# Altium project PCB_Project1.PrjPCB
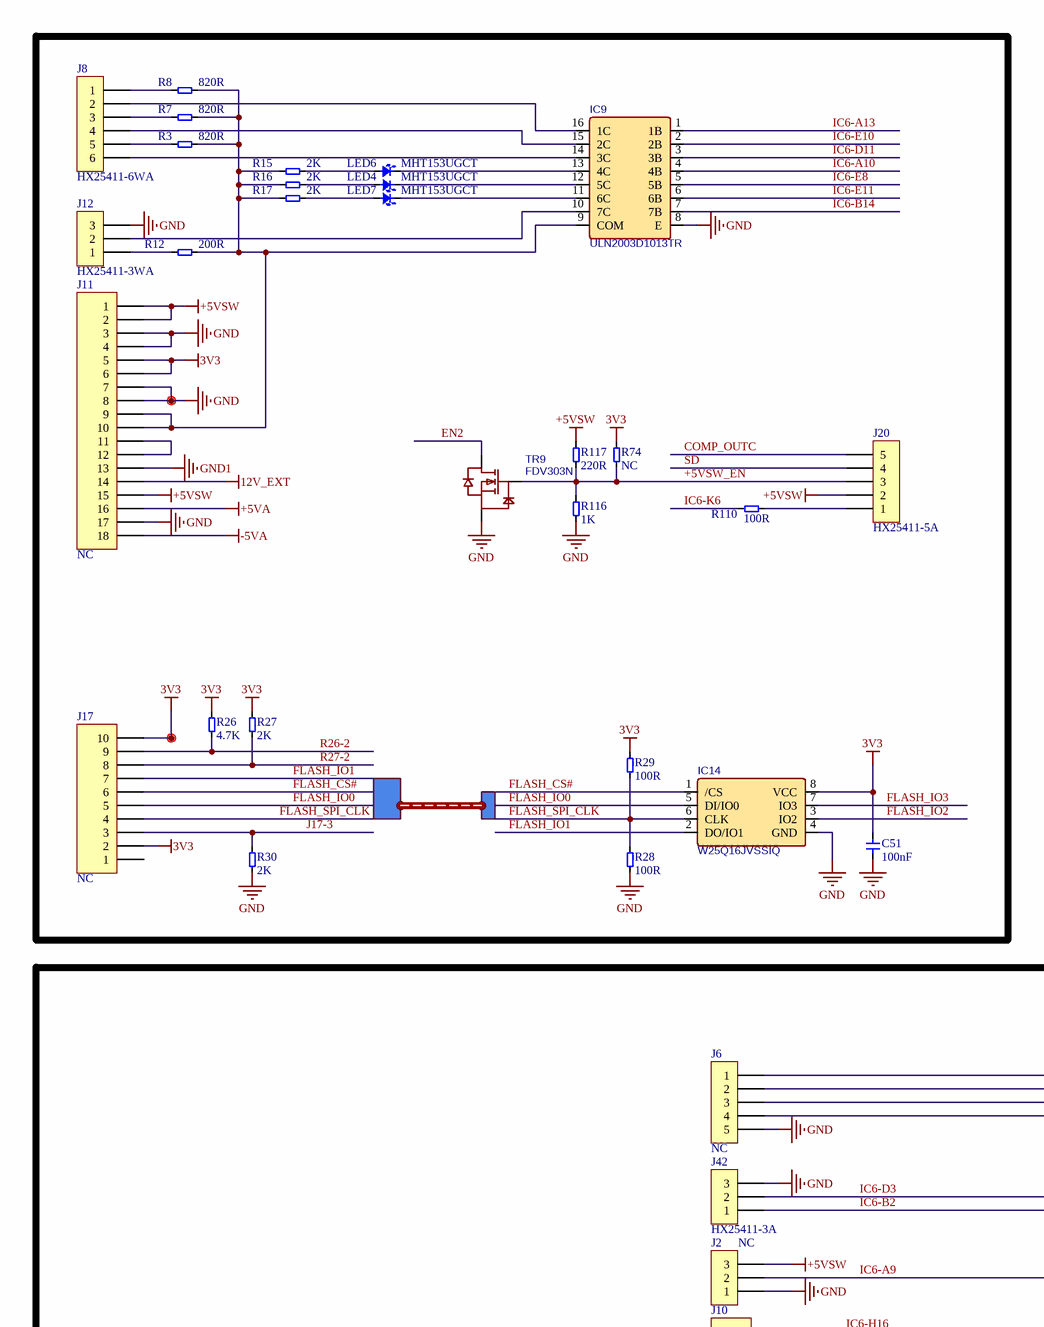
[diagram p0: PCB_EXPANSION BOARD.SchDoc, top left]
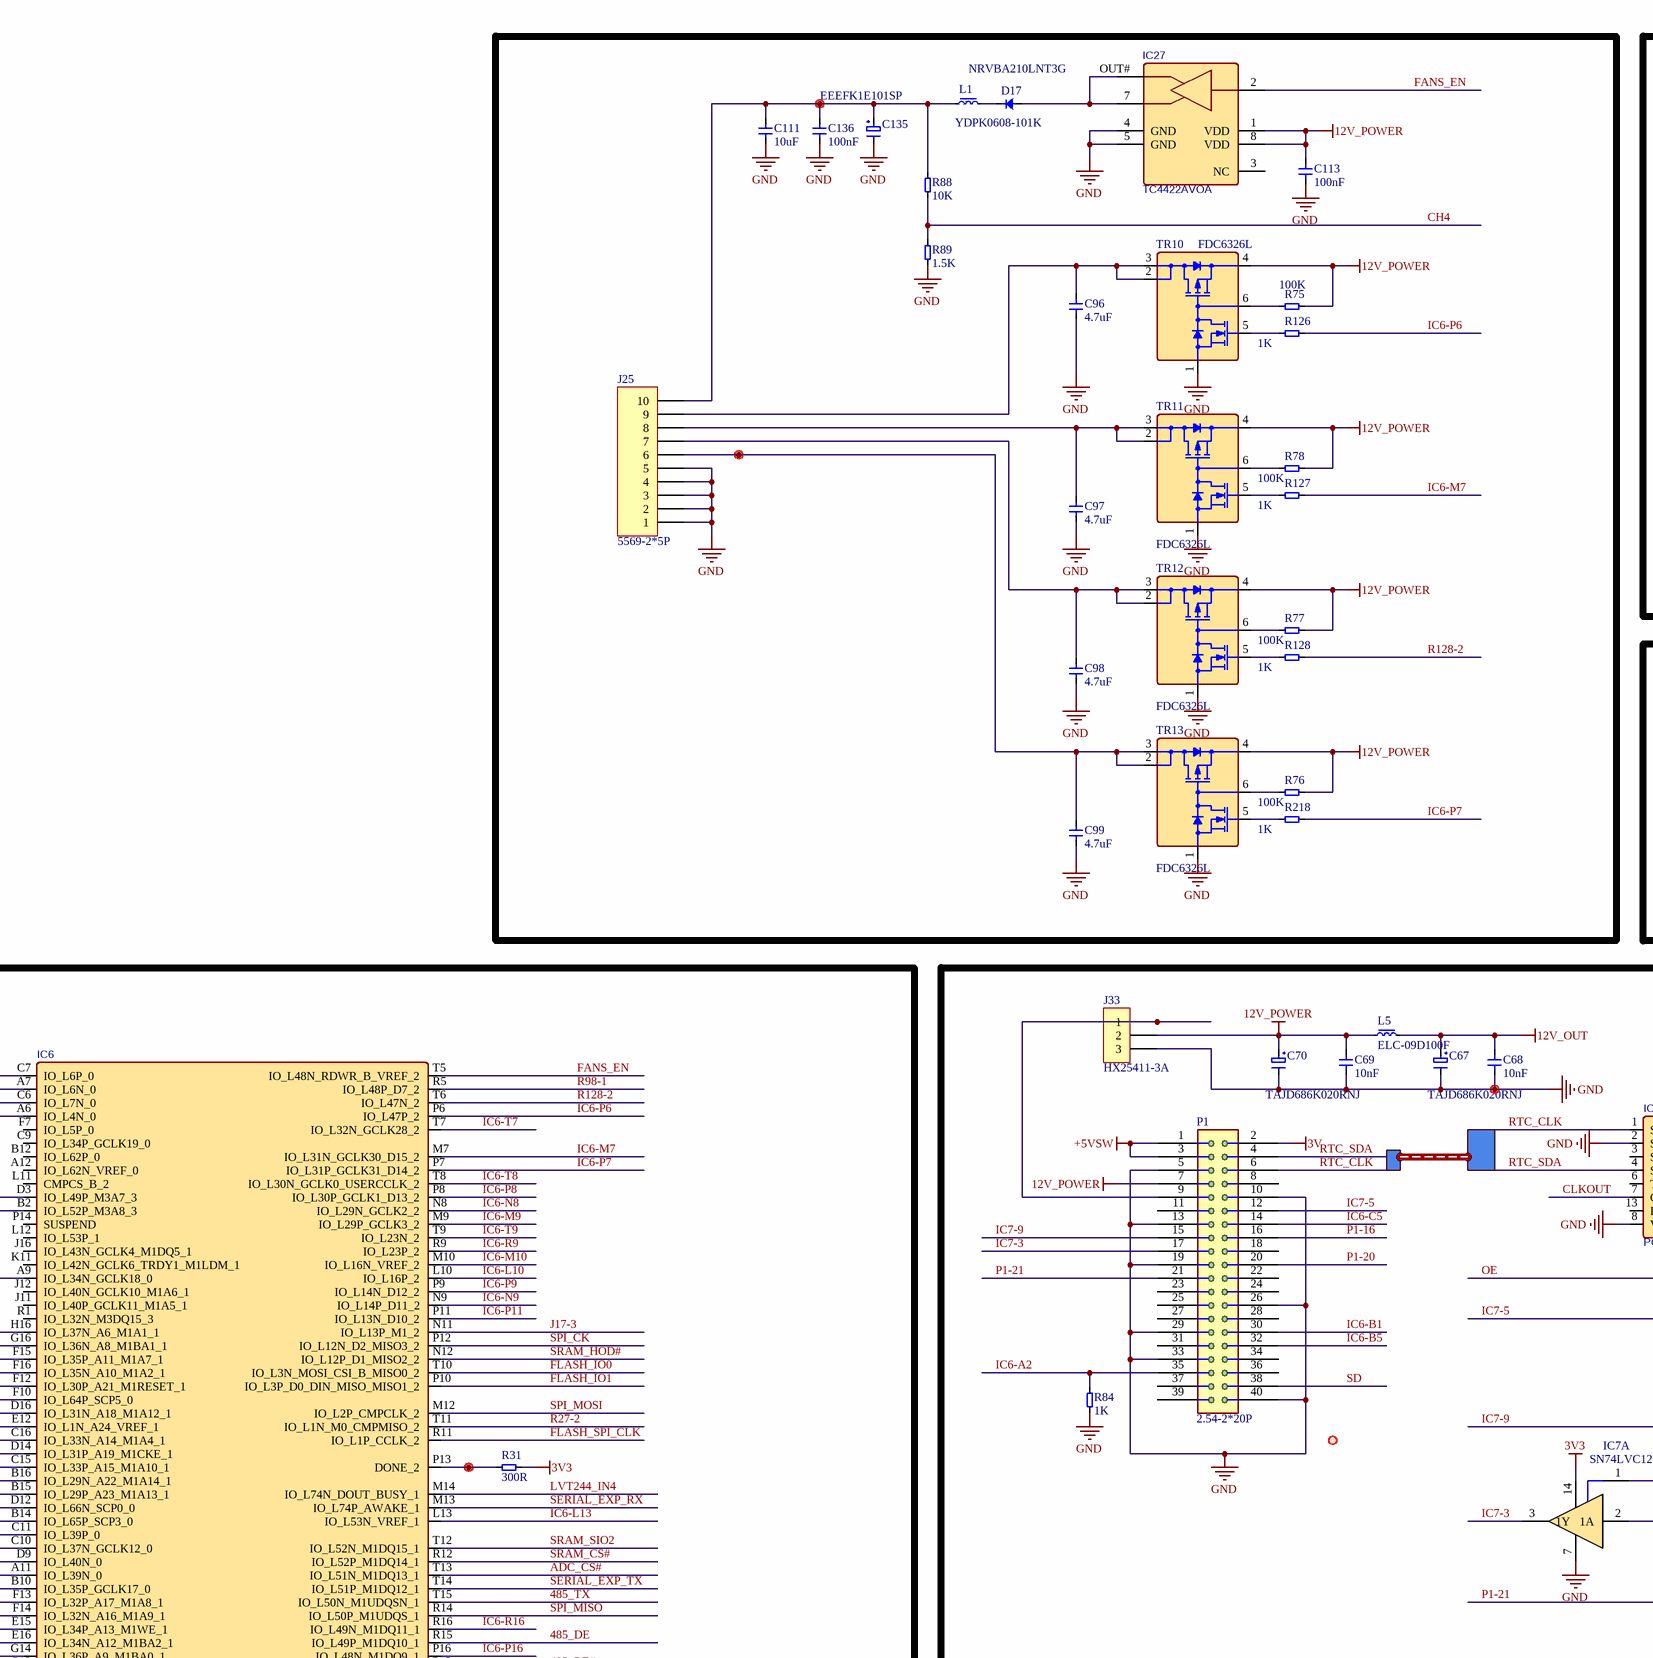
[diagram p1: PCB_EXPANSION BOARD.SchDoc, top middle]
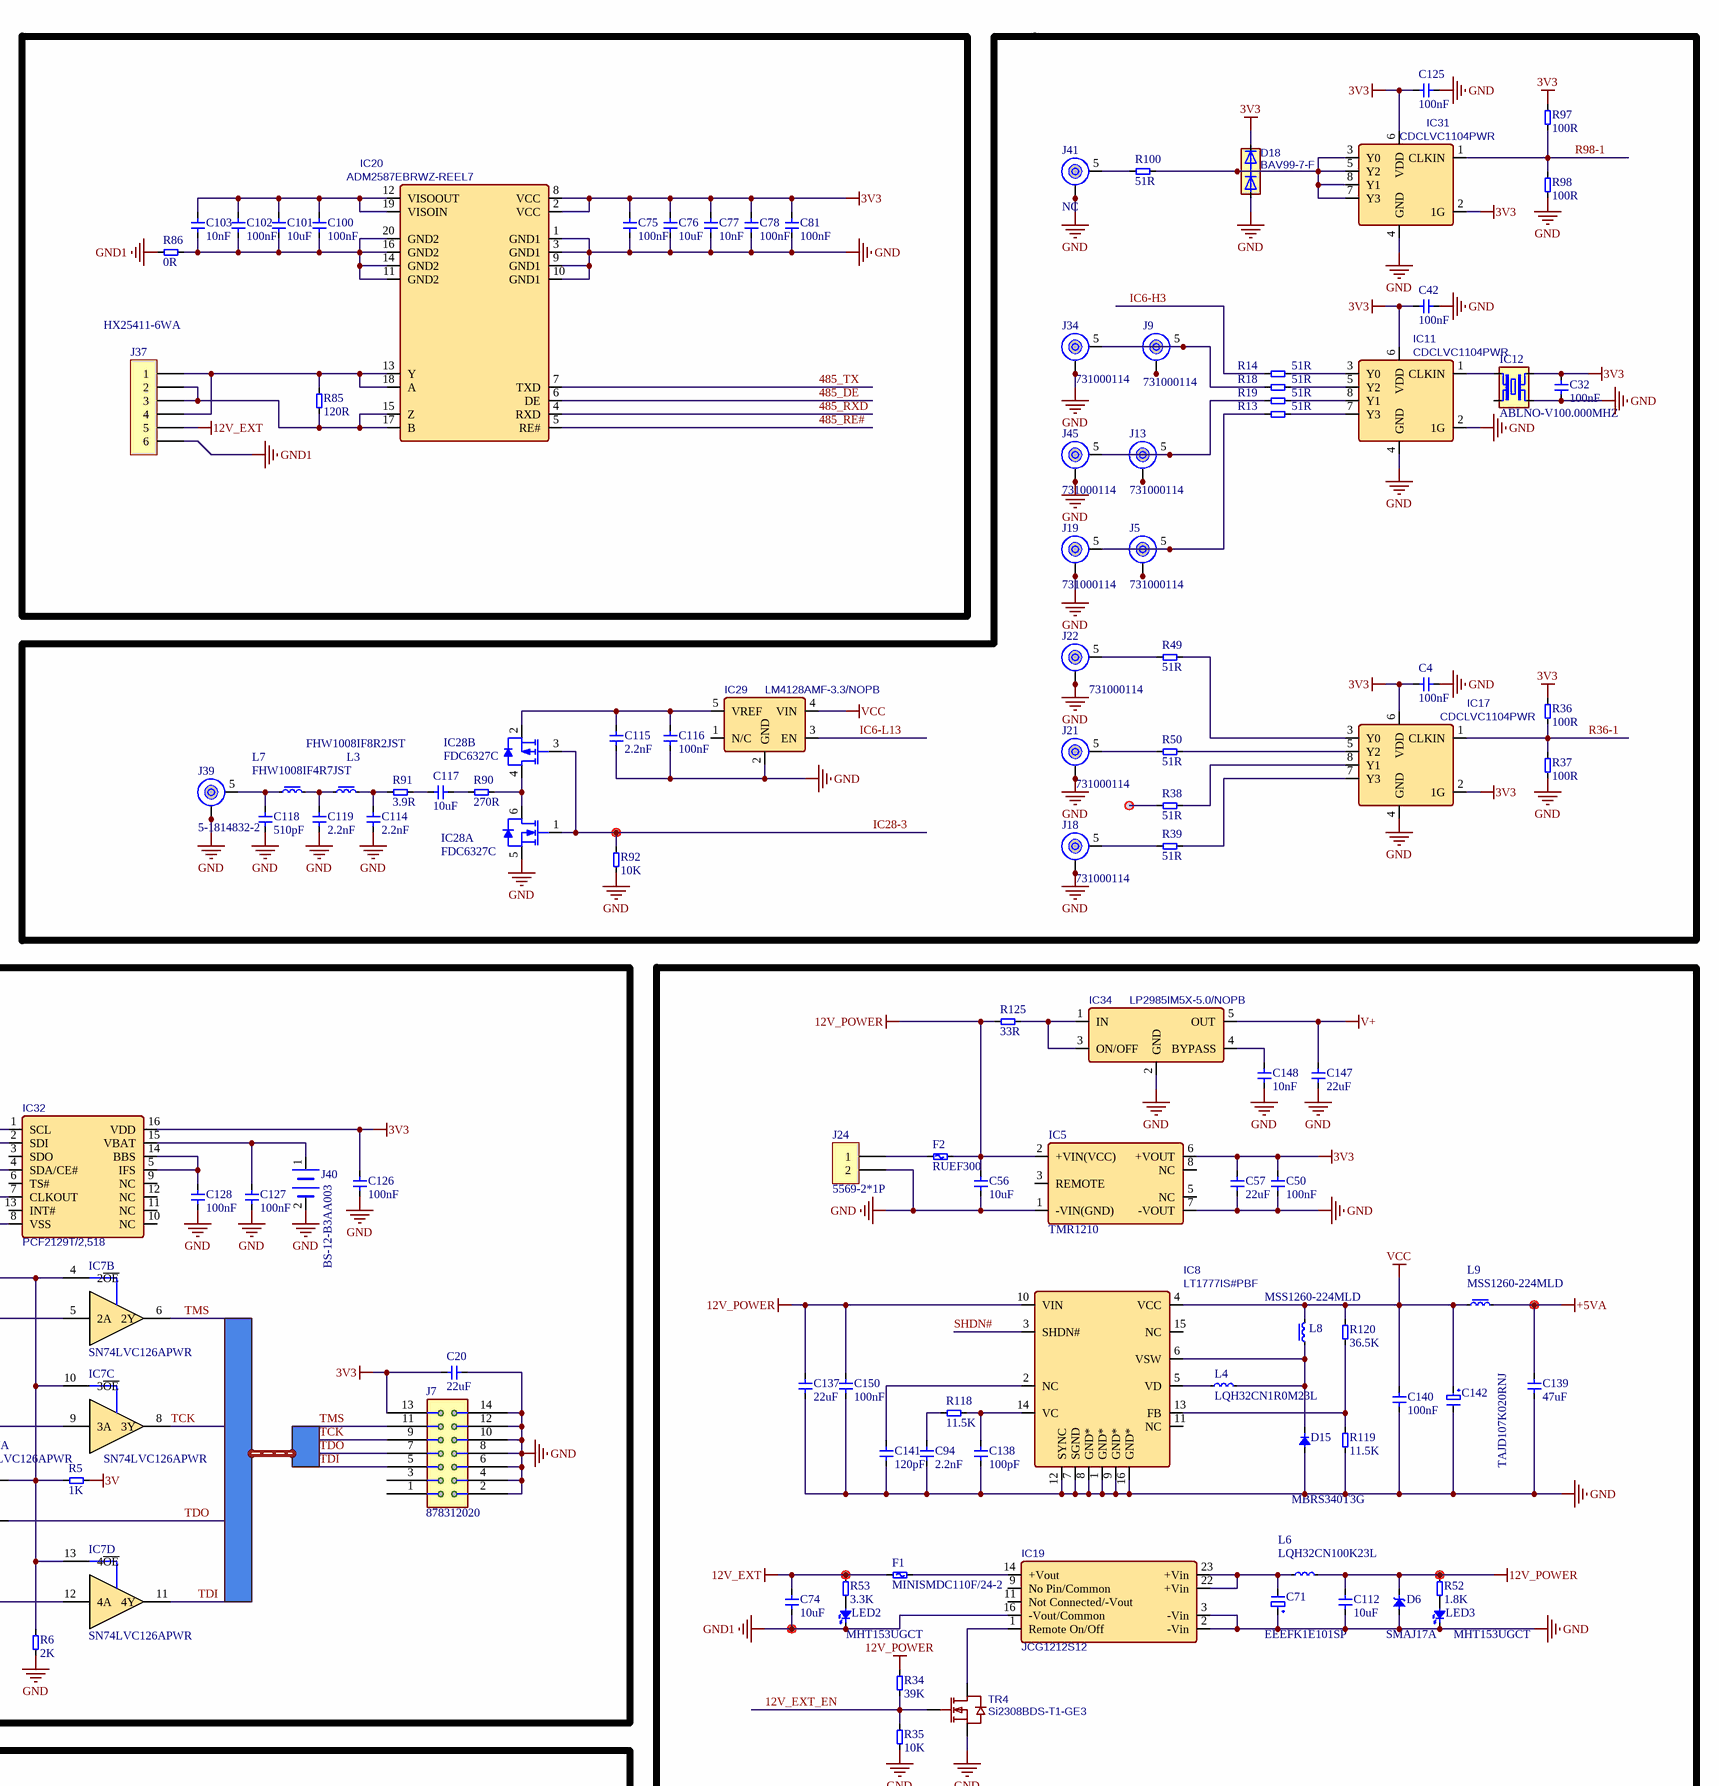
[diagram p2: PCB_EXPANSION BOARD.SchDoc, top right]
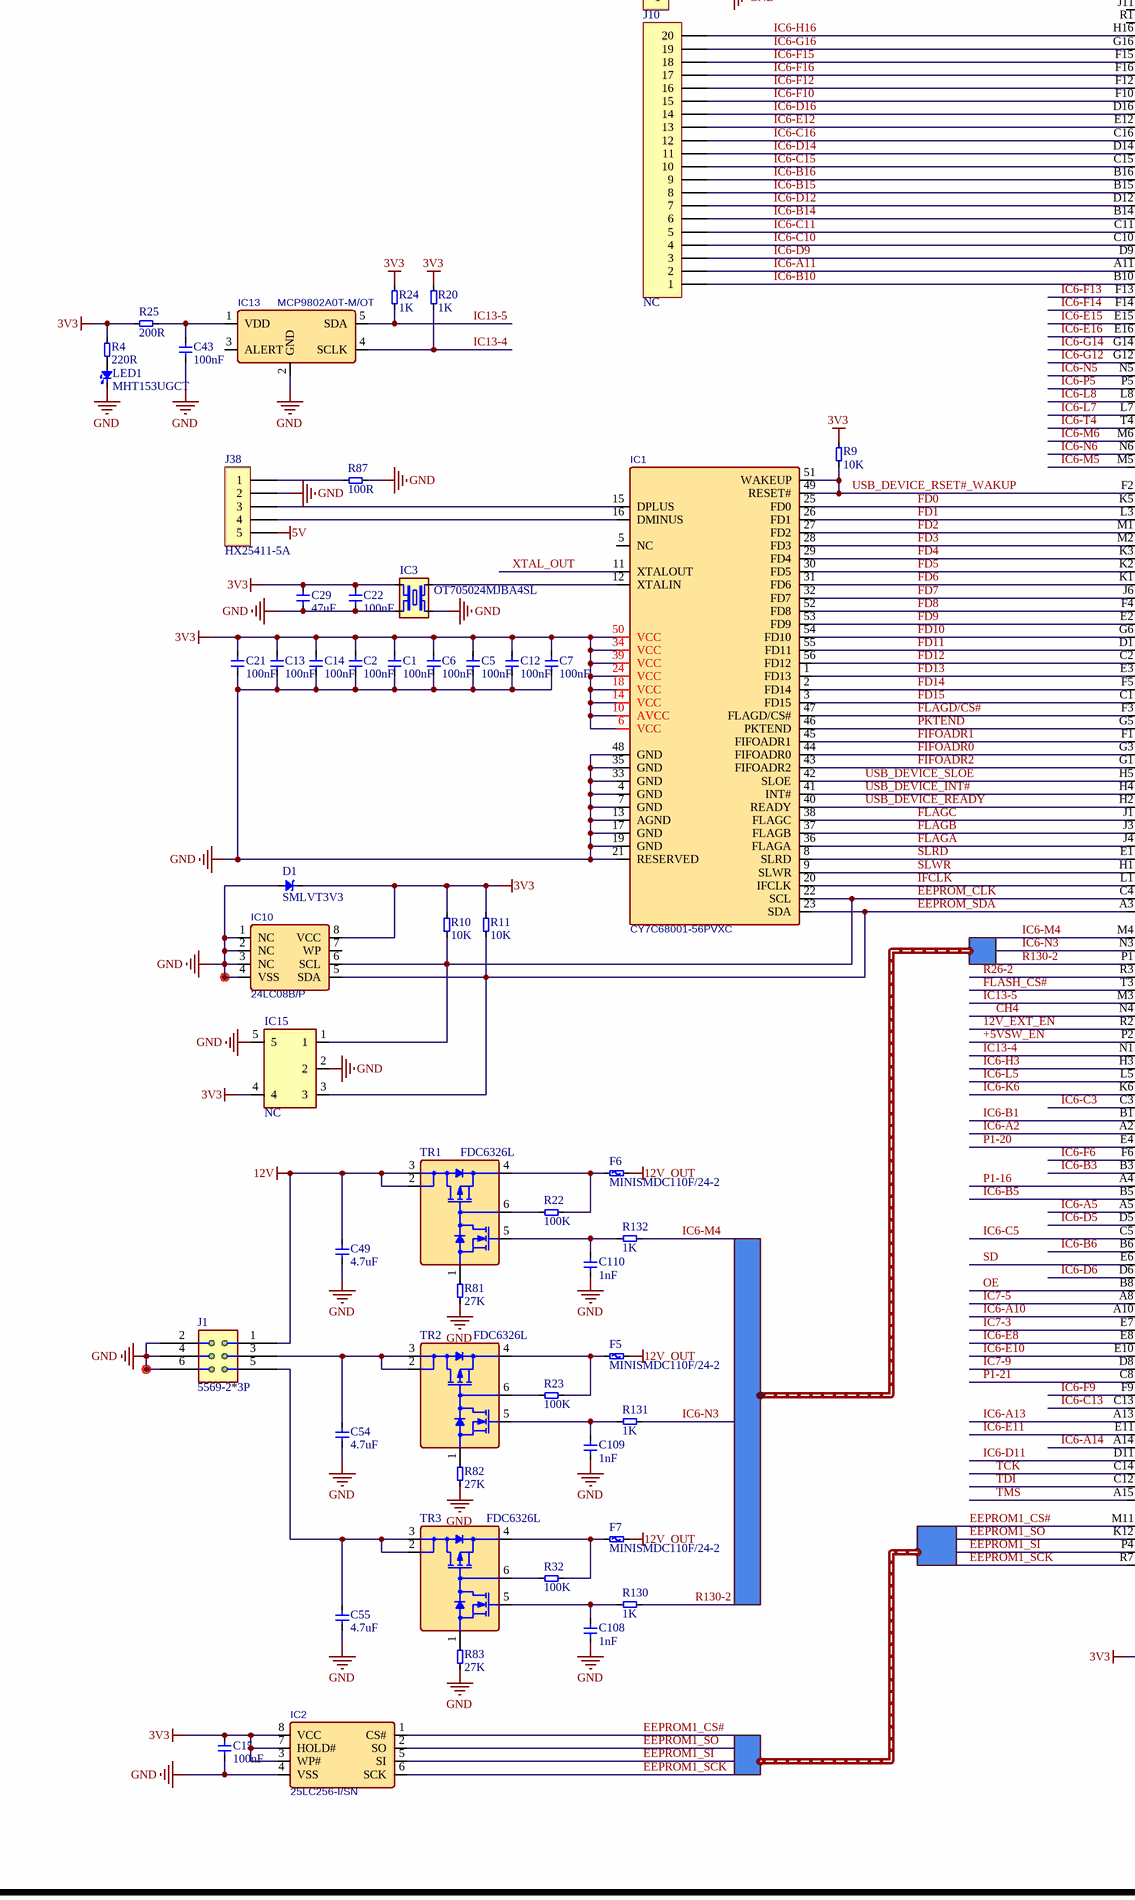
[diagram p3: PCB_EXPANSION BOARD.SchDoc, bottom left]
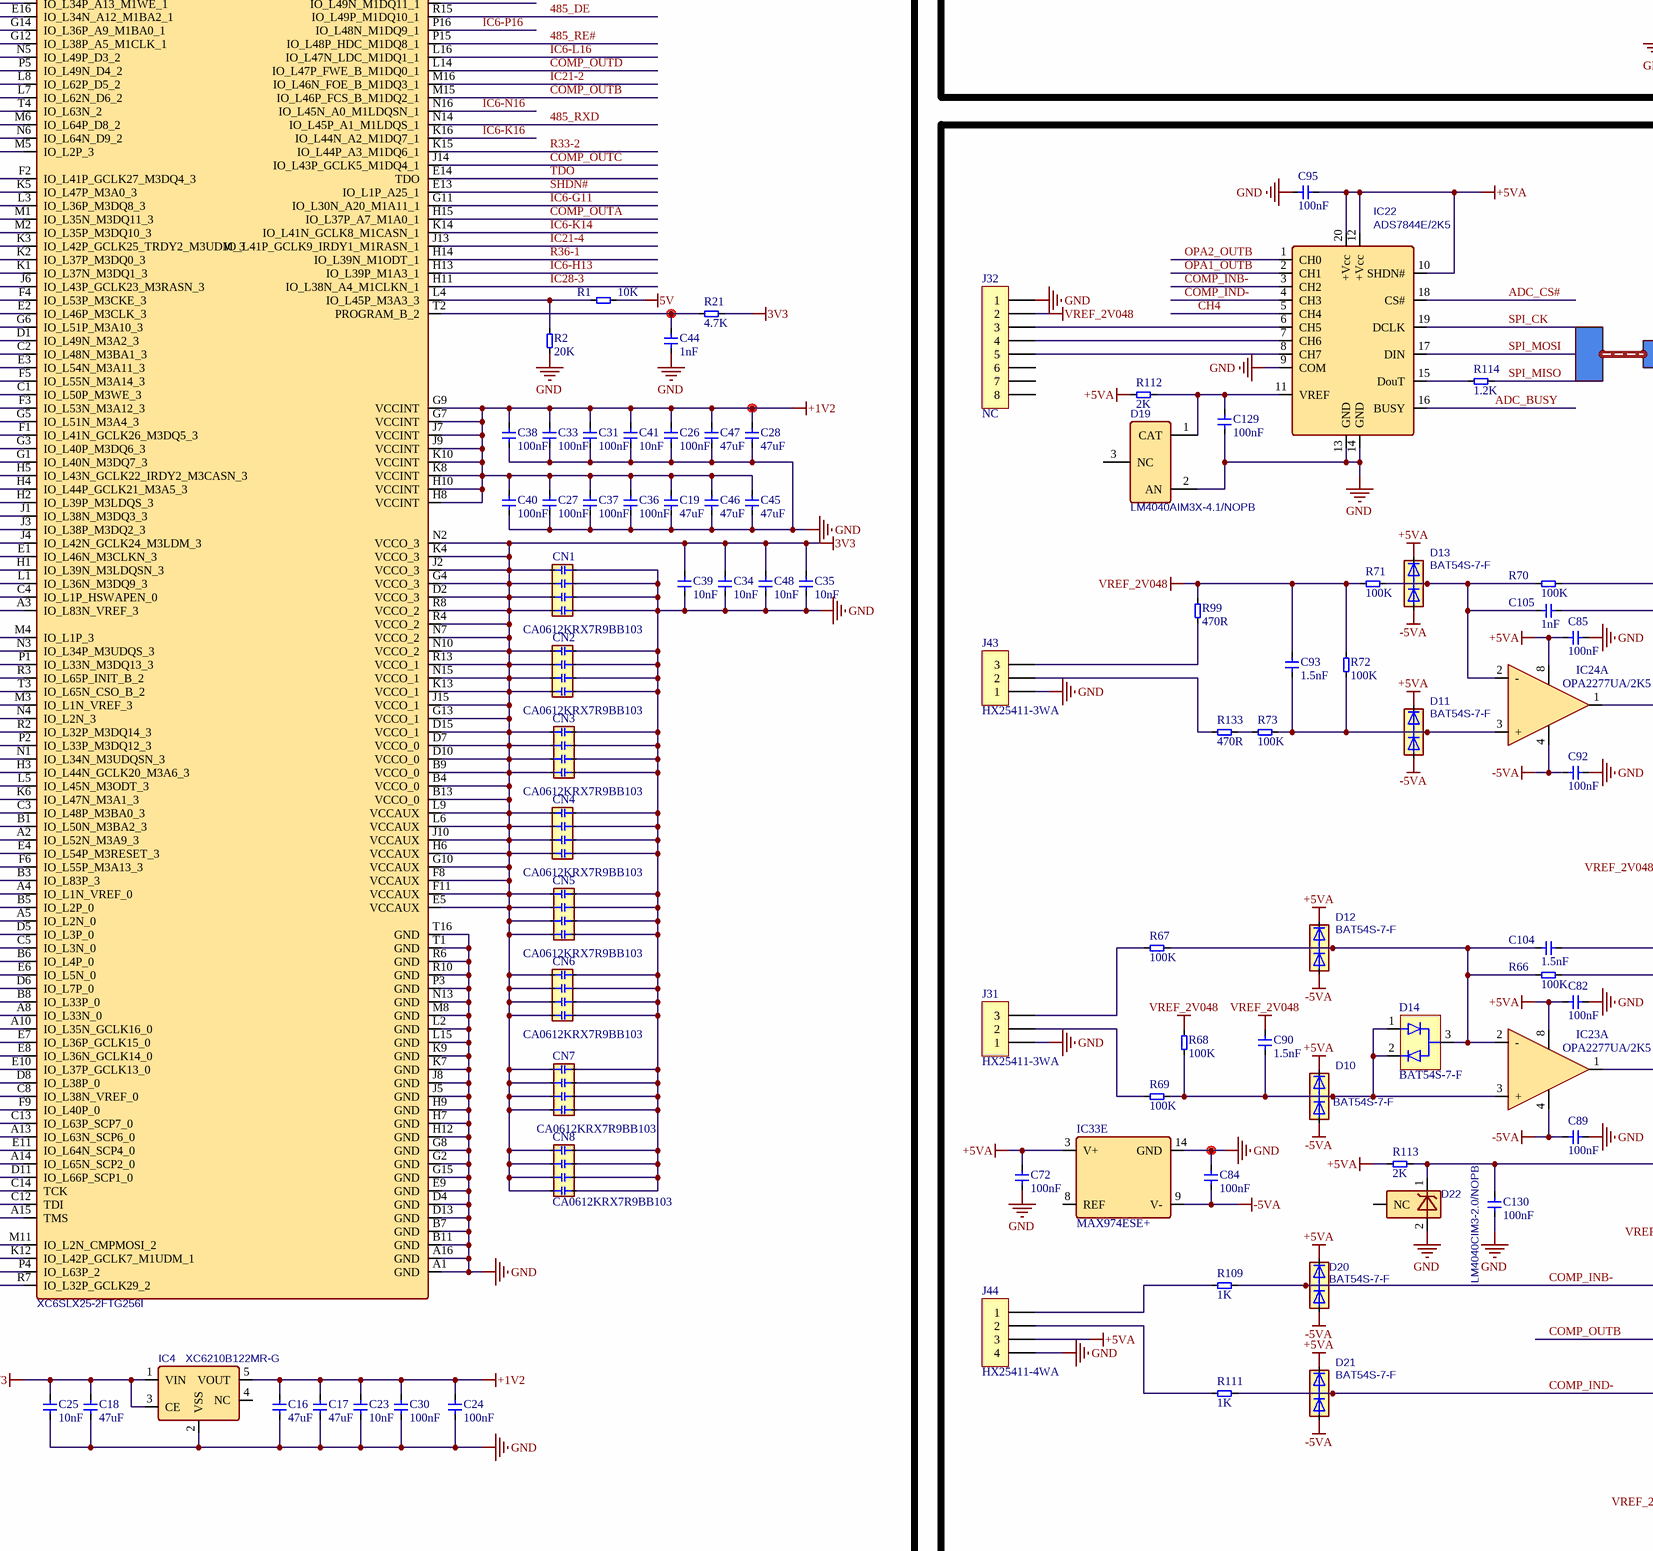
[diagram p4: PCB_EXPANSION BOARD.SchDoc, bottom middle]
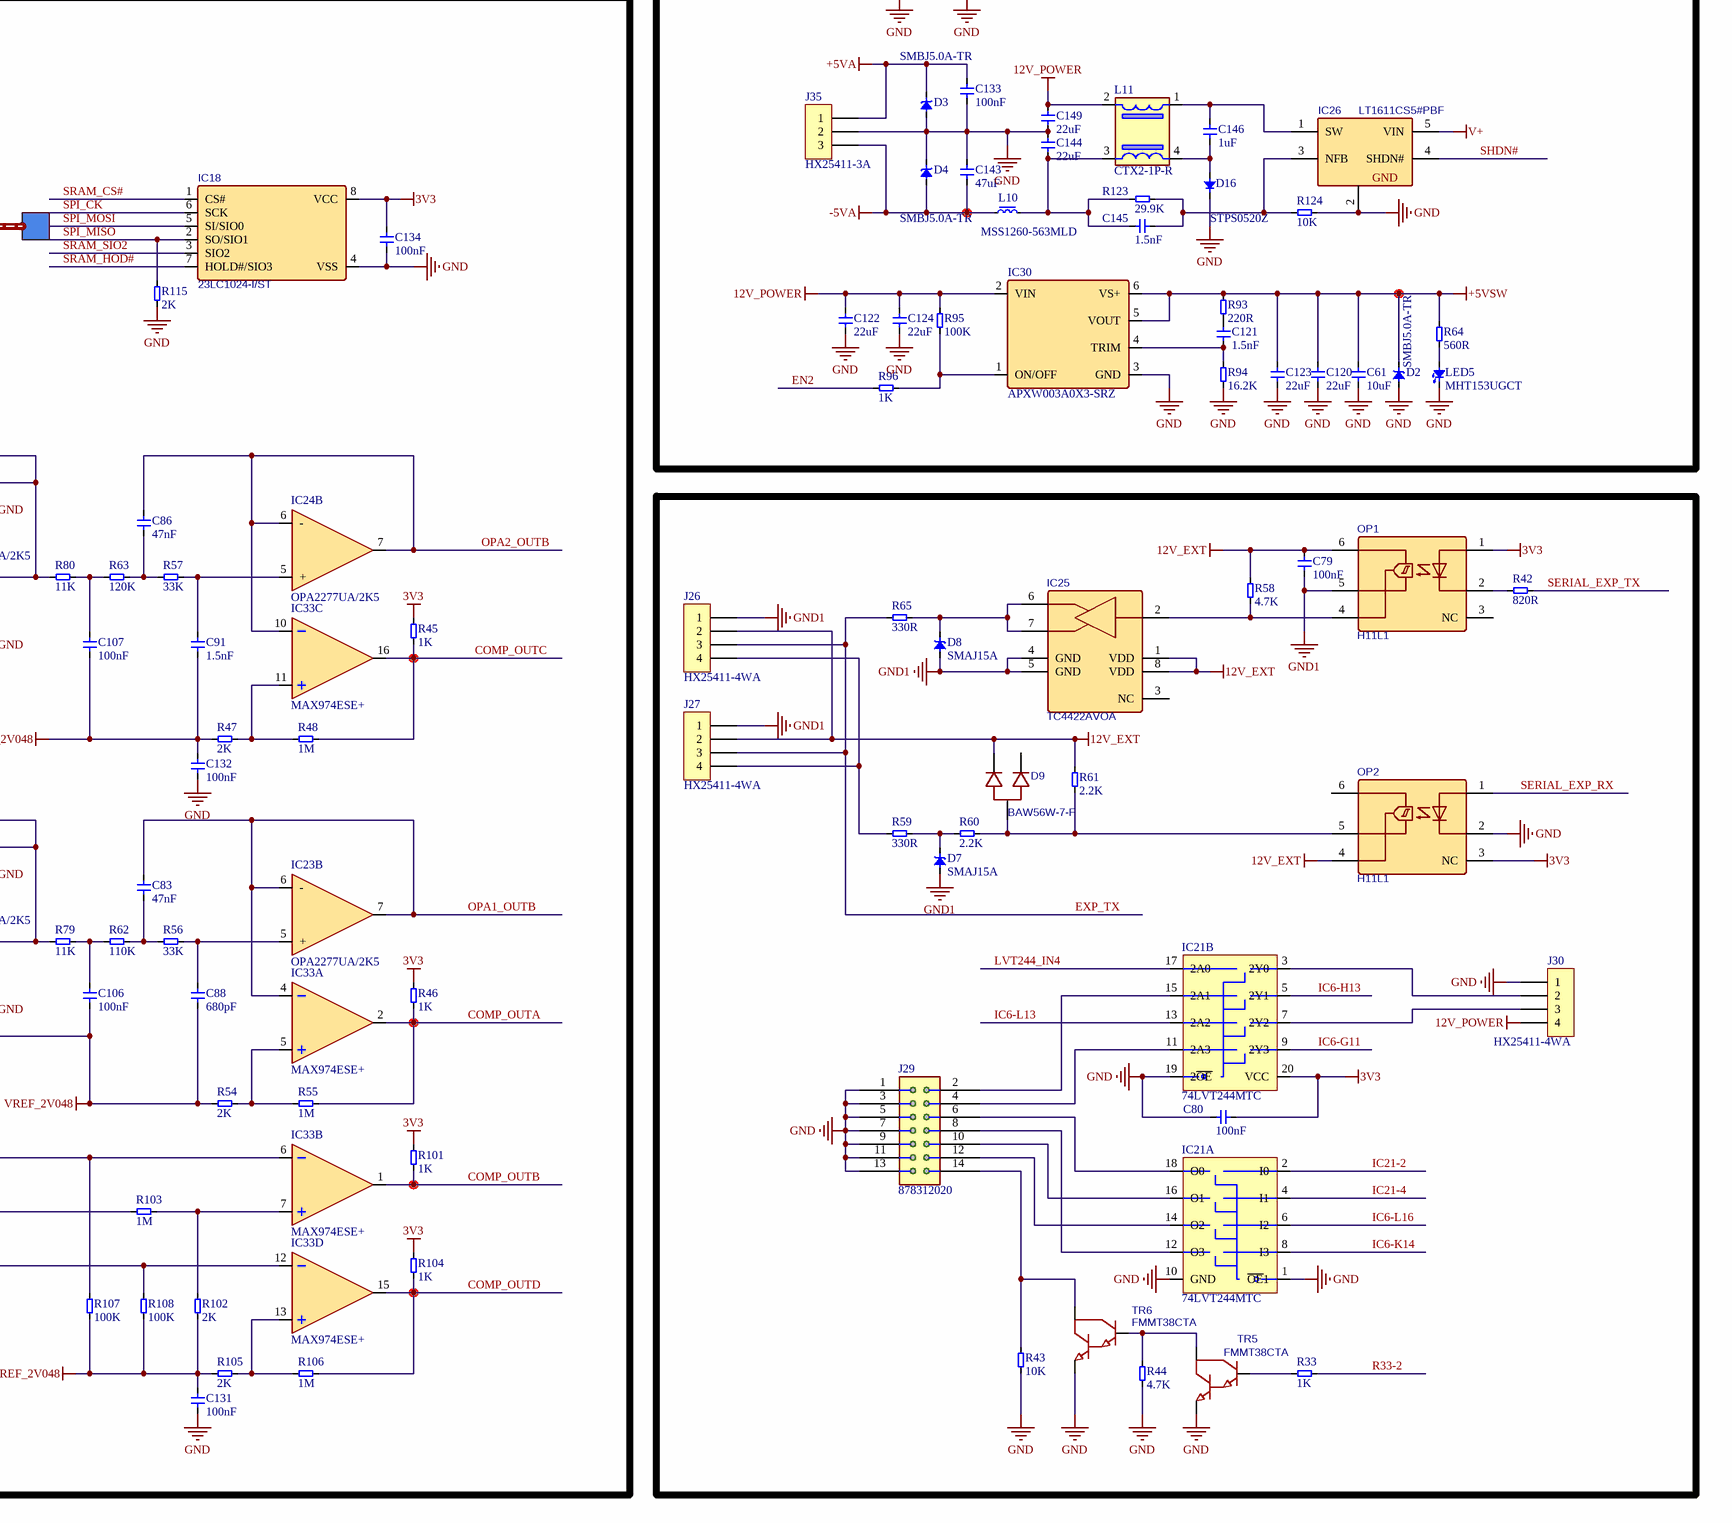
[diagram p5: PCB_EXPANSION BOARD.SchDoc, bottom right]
1 sheet, 420 parts. Net scope: global (net labels, ports and power ports of the same name join across sheets).
Board file: PCB_EXPANSION BOARD.PcbDoc

## Sheet PCB_EXPANSION BOARD.SchDoc
size 861 x 624 mm

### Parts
C1  100nF  [C0603]
C2  100nF  [C0603]
C4  100nF  [C 1206_L]
C5  100nF  [C0603]
C6  100nF  [C0603]
C7  100nF  [C0603]
C12  100nF  [C0603]
C13  100nF  [C0603]
C14  100nF  [C0603]
C15  100nF  [C0603]
C16  47uF  [C 1206_L]
C17  47uF  [C 1206_L]
C18  47uF  [C 1206_L]
C19  47uF  [C 1206_L]
C20  22uF  [C 1206_L]
C21  100nF  [C0603]
C22  100nF  [C0603]
C23  10nF  [C0603]
C24  100nF  [C0603]
C25  10nF  [C0603]
C26  100nF  [C0603]
C27  100nF  [C0603]
C28  47uF  [C 1206_L]
C29  47uF  [C 1206_L]
C30  100nF  [C0603]
C31  100nF  [C0603]
C32  100nF  [C0805]
C33  100nF  [C0603]
C34  10nF  [C0603]
C35  10nF  [C0603]
C36  100nF  [C0603]
C37  100nF  [C0603]
C38  100nF  [C0603]
C39  10nF  [C0603]
C40  100nF  [C0603]
C41  10nF  [C0603]
C42  100nF  [C0805]
C43  100nF  [C0805]
C44  1nF  [C 1206_L]
C45  47uF  [C 1206_L]
C46  47uF  [C 1206_L]
C47  47uF  [C 1206_L]
C48  10nF  [C0603]
C49  4.7uF  [C0805]
C50  100nF  [C0805]
C51  100nF  [C0603]
C54  4.7uF  [C0805]
C55  4.7uF  [C0805]
C56  10uF  [C 1206_L]
C57  22uF  [C 1206_L]
C61  10uF  [C 1206_L]
C67  TAJD686K020RNJ  [C_7343H]
C68  10nF  [C 1206_L]
C69  10nF  [C 1206_L]
C70  TAJD686K020RNJ  [C_7343H]
C71  EEEFK1E101SP  [CAP-SMD_BD6.3]
C72  100nF  [C0603]
C74  10uF  [C 1206_L]
C75  100nF  [C0805]
C76  10uF  [C 1206_L]
C77  10nF  [C0805]
C78  100nF  [C0805]
C79  100nF  [C0805]
C80  100nF  [C0805]
C81  100nF  [C0805]
C82  100nF  [C0603]
C83  47nF  [C0603]
C84  100nF  [C0603]
C85  100nF  [C0603]
C86  47nF  [C0603]
C88  680pF  [C0603]
C89  100nF  [C0603]
C90  1.5nF  [C0603]
C91  1.5nF  [C0603]
C92  100nF  [C0603]
C93  1.5nF  [C0603]
C94  2.2nF  [C0603]
C95  100nF  [C0603]
C96  4.7uF  [C0805]
C97  4.7uF  [C0805]
C98  4.7uF  [C0805]
C99  4.7uF  [C0805]
C100  100nF  [C0805]
C101  10uF  [C 1206_L]
C102  100nF  [C0805]
C103  10nF  [C0805]
C104  1.5nF  [C0603]
C105  1nF  [C0603]
C106  100nF  [C0603]
C107  100nF  [C0603]
C108  1nF  [C0603]
C109  1nF  [C0603]
C110  1nF  [C0603]
C111  10uF  [C1206]
C112  10uF  [C 1206_L]
C113  100nF  [C0603]
C114  2.2nF  [C0603]
C115  2.2nF  [C 1206_L]
C116  100nF  [C0603]
C117  10uF  [C 1206_L]
C118  510pF  [C0805]
C119  2.2nF  [C0603]
C120  22uF  [C 1206_L]
C121  1.5nF  [C0603]
C122  22uF  [C 1206_L]
C123  22uF  [C 1206_L]
C124  22uF  [C 1206_L]
C125  100nF  [C0805]
C126  100nF  [C0805]
C127  100nF  [C0805]
C128  100nF  [C0805]
C129  100nF  [C0603]
C130  100nF  [C0603]
C131  100nF  [C0603]
C132  100nF  [C0603]
C133  100nF  [C0603]
C134  100nF  [C0805]
C135  EEEFK1E101SP  [CAP-SMD_BD6.3]
C136  100nF  [C0603]
C137  22uF  [C 1206_L]
C138  100pF  [C0603]
C139  47uF  [C 1210_L]
C140  100nF  [C0603]
C141  120pF  [C0603]
C142  TAJD107K020RNJ  [C_7343H]
C143  47uF  [C 1210_L]
C144  22uF  [C 1206_L]
C145  1.5nF  [C0603]
C146  1uF  [C0603]
C147  22uF  [C 1206_L]
C148  10nF  [C0603]
C149  22uF  [C 1206_L]
C150  100nF  [C0603]
CN1  CA0612KRX7R9BB103  [CAP-ARRAY-0612-8P]
CN2  CA0612KRX7R9BB103  [CAP-ARRAY-0612-8P]
CN3  CA0612KRX7R9BB103  [CAP-ARRAY-0612-8P]
CN4  CA0612KRX7R9BB103  [CAP-ARRAY-0612-8P]
CN5  CA0612KRX7R9BB103  [CAP-ARRAY-0612-8P]
CN6  CA0612KRX7R9BB103  [CAP-ARRAY-0612-8P]
CN7  CA0612KRX7R9BB103  [CAP-ARRAY-0612-8P]
CN8  CA0612KRX7R9BB103  [CAP-ARRAY-0612-8P]
D1  SMLVT3V3  [SMB]
D2  SMBJ5.0A-TR  [SMB]
D3  SMBJ5.0A-TR  [SMB]
D4  SMBJ5.0A-TR  [SMB]
D6  SMAJ17A  [SMA]
D7  SMAJ15A  [SMA]
D8  SMAJ15A  [SMA]
D9  BAW56W-7-F  [SOT323]
D10  BAT54S-7-F  [SOT-23-3]
D11  BAT54S-7-F  [SOT-23-3]
D12  BAT54S-7-F  [SOT-23-3]
D13  BAT54S-7-F  [SOT-23-3]
D14  BAT54S-7-F  [SOT-23-3]
D15  MBRS340T3G  [SMC]
D16  STPS0520Z  [SOD-123]
D17  NRVBA210LNT3G  [SMA]
D18  BAV99-7-F  [SOT-23-3]
D19  LM4040AIM3X-4.1/NOPB  [SOT-23-3]
D20  BAT54S-7-F  [SOT-23-3]
D21  BAT54S-7-F  [SOT-23-3]
D22  LM4040CIM3-2.0/NOPB  [SOT-23-3]
F1  MINISMDC110F/24-2  [F1812]
F2  RUEF300  [FUSE-TH_L11.2-W3.1]
F5  MINISMDC110F/24-2  [F1812]
F6  MINISMDC110F/24-2  [F1812]
F7  MINISMDC110F/24-2  [F1812]
IC1  CY7C68001-56PVXC  [SSOP-56]
IC2  25LC256-I/SN  [SOIC-8]
IC3  OT705024MJBA4SL  [OSC-SMD_4P-L7.0-W5.0-BL]
IC4  XC6210B122MR-G  [SOT-23-5]
IC5  TMR1210  [PWRM-TH_TRACOPOWER_TMR]
IC6  XC6SLX25-2FTG256I  [FBGA-256_L17.0-W17.0]
IC7  SN74LVC126APWR  [TSSOP14]  (parts A,B,C,D of 4)
IC8  LT1777IS#PBF  [SOP16]
IC9  ULN2003D1013TR  [SOP16]
IC10  24LC08B/P  [DIP-8]
IC11  CDCLVC1104PWR  [TSSOP8]
IC12  ABLNO-V100.000MHZ  [OSC-SMD_4P-L14.3-W8.7-BL]
IC13  MCP9802A0T-M/OT  [SOT-23-5]
IC14  W25Q16JVSSIQ  [SOIC-8W]
IC15  NC  [SOT-23-5]
IC17  CDCLVC1104PWR  [TSSOP8]
IC18  23LC1024-I/ST  [TSSOP8]
IC19  JCG1212S12  [PM_JCG1212S12]
IC20  ADM2587EBRWZ-REEL7  [SOIC-20_L13.0-W7.6]
IC21  74LVT244MTC  [TSSOP20]  (parts A,B of 2)
IC22  ADS7844E/2K5  [SSOP-20]
IC23  OPA2277UA/2K5  [SOIC-8]  (parts A,B of 2)
IC24  OPA2277UA/2K5  [SOIC-8]  (parts A,B of 2)
IC25  TC4422AVOA  [SOIC-8]
IC26  LT1611CS5#PBF  [SOT-23-5]
IC27  TC4422AVOA  [SOIC-8]
IC28  FDC6327C  [SOT-23-6]  (parts A,B of 2)
IC29  LM4128AMF-3.3/NOPB  [SOT-23-5]
IC30  APXW003A0X3-SRZ  [PM_APXW003]
IC31  CDCLVC1104PWR  [TSSOP8]
IC32  PCF2129T/2,518  [SO-16]
IC33  MAX974ESE+  [SOP16]  (parts A,B,C,D,E of 5)
IC34  LP2985IM5X-5.0/NOPB  [SOT-23-5]
J1  5569-2*3P  [CONN-TH_HAA420A-6AW]
J2  NC  [XH2.54-LI-3P]
J5  731000114  [ANT-TH_KH-SMA-K513-G]
J6  NC  [HDR2.54-LI-5P]
J7  878312020  [PHD2.0-LI-2x7P]
J8  HX25411-6WA  [CONN-TH_KF2510-6AGW]
J9  731000114  [ANT-TH_KH-SMA-K513-G]
J10  NC  [HDR2.54-LI-20P]
J11  NC  [HDR2.54-LI-18P]
J12  HX25411-3WA  [CONN-TH_KF2510-3AGW]
J13  731000114  [ANT-TH_KH-SMA-K513-G]
J17  NC  [HDR2.54-LI-10P]
J18  731000114  [ANT-TH_KH-SMA-K513-G]
J19  731000114  [ANT-TH_KH-SMA-K513-G]
J20  HX25411-5A  [KF2510-LI-5P]
J21  731000114  [ANT-TH_KH-SMA-K513-G]
J22  731000114  [ANT-TH_KH-SMA-K513-G]
J24  5569-2*1P  [CONN-TH_2P-P4.20_5557-2X1AW]
J25  5569-2*5P  [CONN-TH_DLL-5569-10AWS]
J26  HX25411-4WA  [CONN-TH_KF2510-4AGW]
J27  HX25411-4WA  [CONN-TH_KF2510-4AGW]
J29  878312020  [PHD2.0-LI-2x7P]
J30  HX25411-4WA  [CONN-TH_KF2510-4AGW]
J31  HX25411-3WA  [CONN-TH_KF2510-3AGW]
J32  NC  [HDR2.54-LI-8P]
J33  HX25411-3A  [KF2510-LI-3P]
J34  731000114  [ANT-TH_KH-SMA-K513-G]
J35  HX25411-3A  [KF2510-LI-3P]
J37  HX25411-6WA  [CONN-TH_KF2510-6AGW]
J38  HX25411-5A  [KF2510-LI-5P]
J39  5-1814832-2  [SMA-TH_BWSMA-KE-Z001]
J40  BS-12-B3AA003  [BAT-SMD_BS-12-B3AA011]
J41  NC  [ANT-TH_KH-SMA-K513-G]
J42  HX25411-3A  [KF2510-LI-3P]
J43  HX25411-3WA  [CONN-TH_KF2510-3AGW]
J44  HX25411-4WA  [CONN-TH_KF2510-4AGW]
J45  731000114  [ANT-TH_KH-SMA-K513-G]
L1  YDPK0608-101K  [PK0810]
L3  FHW1008IF8R2JST  [IND-SMD_2520]
L4  LQH32CN1R0M23L  [IND-SMD_3225]
L5  ELC-09D100F  [PK0810]
L6  LQH32CN100K23L  [IND-SMD_3225]
L7  FHW1008IF4R7JST  [IND-SMD_2520]
L8  MSS1260-224MLD  [IND-SMD_L12.0-W12.0]
L9  MSS1260-224MLD  [IND-SMD_L12.0-W12.0]
L10  MSS1260-563MLD  [IND-SMD_L12.0-W12.0]
L11  CTX2-1P-R  [IND_CB_CTX-1]
LED1  MHT153UGCT  [LED1206-RD_GREEN]
LED2  MHT153UGCT  [LED1206-RD_GREEN]
LED3  MHT153UGCT  [LED1206-RD_GREEN]
LED4  MHT153UGCT  [LED1206-RD_GREEN]
LED5  MHT153UGCT  [LED1206-RD_GREEN]
LED6  MHT153UGCT  [LED1206-RD_GREEN]
LED7  MHT153UGCT  [LED1206-RD_GREEN]
OP1  H11L1  [DIP-6_L8.5-W6.4-P2.54-LS7.6-BL]
OP2  H11L1  [DIP-6_L8.5-W6.4-P2.54-LS7.6-BL]
P1  2.54-2*20P  [HDR2.54-LI-2x20P]
R1  10K  [R0603]
R2  20K  [R0603]
R3  820R  [R0805]
R4  220R  [R0805]
R5  1K  [R0603]
R6  2K  [R0603]
R7  820R  [R0805]
R8  820R  [R0805]
R9  10K  [R0603]
R10  10K  [R0603]
R11  10K  [R0603]
R12  200R  [R0805]
R13  51R  [R0805]
R14  51R  [R0805]
R15  2K  [R0805]
R16  2K  [R0805]
R17  2K  [R0805]
R18  51R  [R0805]
R19  51R  [R0805]
R20  1K  [R0805]
R21  4.7K  [R0603]
R22  100K  [R0603]
R23  100K  [R0603]
R24  1K  [R0805]
R25  200R  [R0805]
R26  4.7K  [R0603]
R27  2K  [R0603]
R28  100R  [R0603]
R29  100R  [R0603]
R30  2K  [R0603]
R31  300R  [R0603]
R32  100K  [R0603]
R33  1K  [R0805]
R34  39K  [R0805]
R35  10K  [R0805]
R36  100R  [R0805]
R37  100R  [R0805]
R38  51R  [R0805]
R39  51R  [R0805]
R42  820R  [R0805]
R43  10K  [R0805]
R44  4.7K  [R0805]
R45  1K  [R0603]
R46  1K  [R0603]
R47  2K  [R0603]
R48  1M  [R0603]
R49  51R  [R0805]
R50  51R  [R0805]
R52  1.8K  [R0805]
R53  3.3K  [R0805]
R54  2K  [R0603]
R55  1M  [R0603]
R56  33K  [R0603]
R57  33K  [R0603]
R58  4.7K  [R0805]
R59  330R  [R0805]
R60  2.2K  [R0805]
R61  2.2K  [R0805]
R62  110K  [R0603]
R63  120K  [R0603]
R64  560R  [R0805]
R65  330R  [R0805]
R66  100K  [R0603]
R67  100K  [R1206]
R68  100K  [R1206]
R69  100K  [R1206]
R70  100K  [R0603]
R71  100K  [R0603]
R72  100K  [R0603]
R73  100K  [R0603]
R74  NC  [R0805]
R75  100K  [R0603]
R76  100K  [R0603]
R77  100K  [R0603]
R78  100K  [R0603]
R79  11K  [R0603]
R80  11K  [R0603]
R81  27K  [R0603]
R82  27K  [R0603]
R83  27K  [R0603]
R84  1K  [R0603]
R85  120R  [R0805]
R86  0R  [R0805]
R87  100R  [R0603]
R88  10K  [R0603]
R89  1.5K  [R0603]
R90  270R  [R0603]
R91  3.9R  [R0603]
R92  10K  [R0603]
R93  220R  [R0603]
R94  16.2K  [R0603]
R95  100K  [R0603]
R96  1K  [R0603]
R97  100R  [R0805]
R98  100R  [R0805]
R99  470R  [R0603]
R100  51R  [R0805]
R101  1K  [R0603]
R102  2K  [R0603]
R103  1M  [R0603]
R104  1K  [R0603]
R105  2K  [R0603]
R106  1M  [R0603]
R107  100K  [R0603]
R108  100K  [R0603]
R109  1K  [R0603]
R110  100R  [R0603]
R111  1K  [R0603]
R112  2K  [R0603]
R113  2K  [R0603]
R114  1.2K  [R0603]
R115  2K  [R0603]
R116  1K  [R0603]
R117  220R  [R0603]
R118  11.5K  [R0603]
R119  11.5K  [R0603]
R120  36.5K  [R0603]
R123  29.9K  [R0603]
R124  10K  [R0603]
R125  33R  [R0603]
R126  1K  [R0603]
R127  1K  [R0603]
R128  1K  [R0603]
R130  1K  [R0603]
R131  1K  [R0603]
R132  1K  [R0603]
R133  470R  [R0603]
R218  1K  [R0603]
TP1  NC  [TEST_HOLE_C2mmD1mm]  (value not drawn)
TP2  NC  [TEST_HOLE_C2mmD1mm]  (value not drawn)
TP4  NC  [TEST_HOLE_C2mmD1mm]  (value not drawn)
TP5  NC  [TEST_HOLE_C2mmD1mm]  (value not drawn)
TP6  NC  [TEST_HOLE_C2mmD1mm]  (value not drawn)
TP7  NC  [TEST_HOLE_C2mmD1mm]  (value not drawn)
TP8  NC  [TEST_HOLE_C2mmD1mm]  (value not drawn)
TP9  NC  [TEST_HOLE_C2mmD1mm]  (value not drawn)
TP10  NC  [TEST_HOLE_C2mmD1mm]  (value not drawn)
TP11  NC  [TEST_HOLE_C2mmD1mm]  (value not drawn)
TP12  NC  [TEST_HOLE_C2mmD1mm]  (value not drawn)
TP13  NC  [TEST_HOLE_C2mmD1mm]  (value not drawn)
TP14  NC  [TEST_HOLE_C2mmD1mm]  (value not drawn)
TP15  NC  [TEST_HOLE_C2mmD1mm]  (value not drawn)
TP16  NC  [TEST_HOLE_C2mmD1mm]  (value not drawn)
TP17  NC  [TEST_HOLE_C2mmD1mm]  (value not drawn)
TP18  NC  [TEST_HOLE_C2mmD1mm]  (value not drawn)
TP19  NC  [TEST_HOLE_C2mmD1mm]  (value not drawn)
TP20  NC  [TEST_HOLE_C2mmD1mm]  (value not drawn)
TP21  NC  [TEST_HOLE_C2mmD1mm]  (value not drawn)
TP22  NC  [TEST_HOLE_C2mmD1mm]  (value not drawn)
TP24  NC  [TEST_HOLE_C2mmD1mm]  (value not drawn)
TP25  NC  [TEST_HOLE_C2mmD1mm]  (value not drawn)
TP111  NC  [TEST_HOLE_C2mmD1mm]  (value not drawn)
TR1  FDC6326L  [SOT-23-6]
TR2  FDC6326L  [SOT-23-6]
TR3  FDC6326L  [SOT-23-6]
TR4  Si2308BDS-T1-GE3  [SOT-23-3]
TR5  FMMT38CTA  [SOT-23-3]
TR6  FMMT38CTA  [SOT-23-3]
TR9  FDV303N  [SOT-23-3]
TR10  FDC6326L  [SOT-23-6]
TR11  FDC6326L  [SOT-23-6]
TR12  FDC6326L  [SOT-23-6]
TR13  FDC6326L  [SOT-23-6]

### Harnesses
*: 

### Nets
3V: P1.2 R5.2
3V3: C1.1 C2.2 C4.2 C5.2 C6.2 C7.2 C12.1 C13.2 C14.2 C15.1 C18.1 C20.2 C21.1 C22.1 C25.1 C29.2 C32.2 C34.1 C35.2 C39.2 C42.1 C48.2 C50.2 C51.1 C57.1 C75.2 C76.2 C77.2 C78.2 C80.1 C81.1 C125.1 C126.2 C134.2 CN1.5 CN1.6 CN1.7 CN1.8 CN2.5 CN2.6 CN2.7 CN2.8 CN3.1 CN3.2 CN3.3 CN3.4 CN4.5 CN4.6 CN4.7 CN4.8 CN5.1 CN5.2 CN5.3 CN5.4 CN6.5 CN6.6 CN6.7 CN6.8 CN7.1 CN7.2 CN7.3 CN7.4 CN8.1 CN8.2 CN8.3 CN8.4 D1.1 D18.2 IC1.6(VCC) IC1.10(AVCC) IC1.14(VCC) IC1.18(VCC) IC1.24(VCC) IC1.34(VCC) IC1.39(VCC) IC1.50(VCC) IC2.3(WP#) IC2.7(HOLD#) IC2.8(VCC) IC3.4 IC4.1(VIN) IC4.3(CE) IC5.6(+VOUT) IC6.B4(VCCO_0) IC6.B9(VCCO_0) IC6.B13(VCCO_0) IC6.D2(VCCO_3) IC6.D7(VCCO_0) IC6.D10(VCCO_0) IC6.D15(VCCO_1) IC6.E5(VCCAUX) IC6.F8(VCCAUX) IC6.F11(VCCAUX) IC6.G4(VCCO_3) IC6.G10(VCCAUX) IC6.G13(VCCO_1) IC6.H6(VCCAUX) IC6.J2(VCCO_3) IC6.J10(VCCAUX) IC6.J15(VCCO_1) IC6.K4(VCCO_3) IC6.K13(VCCO_1) IC6.L6(VCCAUX) IC6.L9(VCCAUX) IC6.N2(VCCO_3) IC6.N7(VCCO_2) IC6.N10(VCCO_2) IC6.N15(VCCO_1) IC6.R4(VCCO_2) IC6.R8(VCCO_2) IC6.R13(VCCO_1) IC7.14(VCC) IC10.8(VCC) IC11.6(VDD) IC12.4 IC14.8(VCC) IC15.4 IC17.2(1G) IC17.6(VDD) IC18.8(VCC) IC20.2(VCC) IC20.8(VCC) IC21.20(VCC) IC31.2(1G) IC31.6(VDD) IC32.16(VDD) J7.13 J11.5 J11.6 J17.2 J17.10 OP1.1(AN) OP2.3(NC) R4.2 R9.1 R10.2 R11.2 R20.1 R21.1 R24.1 R25.2 R26.1 R27.1 R29.1 R31.2 R36.2 R45.1 R46.1 R74.1 R97.1 R101.1 R104.2 TP5.1
5V: J38.5 R1.1
12V: C49.2 J1.1 TR1.2 TR1.3
12V_EXT: C74.1 C79.2 D9.2(C2) F1.1 IC25.1(VDD) IC25.8(VDD) J11.14 J26.2 J27.2 J37.5 OP1.6(VCC) OP2.4(VO) R53.2 R58.1 R61.2 TP14.1
12V_OUT: C67.1 C68.1 F5.1 F6.1 F7.1 L5.1
12V_POWER: C56.1 C69.1 C70.1 C112.1 C113.2 C122.1 C124.1 C137.1 C149.1 C150.1 D6.1 F2.1 IC5.2(+VIN(VCC)) IC8.10(VIN) IC27.1(VDD) IC27.8(VDD) IC30.2(VIN) J30.4 J33.2 L5.2 L6.2 L11.2 P1.7 R34.2 R52.1 R75.1 R76.1 R77.1 R78.1 R95.2 R125.2 TP12.1 TR10.4 TR11.4 TR12.4 TR13.4
+1V2: C16.2 C17.1 C19.2 C23.1 C24.1 C26.1 C27.1 C28.2 C30.1 C31.1 C33.1 C36.2 C37.2 C38.2 C40.1 C41.1 C45.2 C46.2 C47.2 IC4.5(VOUT) IC6.G7(VCCINT) IC6.G9(VCCINT) IC6.H8(VCCINT) IC6.H10(VCCINT) IC6.J7(VCCINT) IC6.J9(VCCINT) IC6.K8(VCCINT) IC6.K10(VCCINT) TP4.1
+5VA: C72.2 C82.1 C85.2 C95.1 C133.2 C139.1 D3.1 D10.2 D11.2 D12.2 D13.2 D20.2 D21.2 IC22.10(SHDN#) IC22.12(+Vcc) IC22.20(+Vcc) IC23.8(VCC) IC24.8(VCC) IC33.3(V+) J11.16 J35.1 J44.3 L9.2 R112.2 R113.2 TP8.1
+5VSW: C61.1 C120.2 C123.2 D2.1 IC30.5(VOUT) IC30.6(VS+) J2.3 J11.1 J11.2 J11.15 J20.2 P1.1 P1.3 R64.1 R93.2 R117.2 TP13.1
-5VA: C84.2 C89.1 C92.1 C143.1 D4.2 D10.1 D11.1 D12.1 D13.1 D20.1 D21.1 IC23.4(GND) IC24.4(GND) IC33.9(V-) J11.18 J35.3 L10.2 TP10.1
GND: C1.2 C2.1 C4.1 C5.1 C6.1 C7.1 C12.2 C13.1 C14.1 C15.2 C16.1 C17.2 C18.2 C19.1 C20.1 C21.2 C22.2 C23.2 C24.2 C25.2 C26.2 C27.2 C28.1 C29.1 C30.2 C31.2 C32.1 C33.2 C34.2 C35.1 C36.1 C37.1 C38.1 C39.1 C40.2 C41.2 C42.2 C43.2 C44.1 C45.1 C46.1 C47.1 C48.1 C49.1 C50.1 C51.2 C54.2 C55.1 C56.2 C57.2 C61.2 C67.2 C68.2 C69.2 C70.2 C71.1 C72.1 C75.1 C76.1 C77.1 C78.1 C80.2 C81.2 C82.2 C84.1 C85.1 C89.2 C92.2 C94.1 C95.2 C96.1 C97.1 C98.1 C99.2 C108.2 C109.2 C110.2 C111.1 C112.2 C113.1 C114.1 C115.1 C116.1 C118.2 C119.2 C120.1 C122.2 C123.1 C124.2 C125.2 C126.1 C127.1 C128.1 C129.2 C130.1 C131.1 C132.2 C133.1 C134.1 C135.2 C136.1 C137.2 C138.2 C139.2 C140.1 C141.1 C142.2 C143.2 C144.1 C147.2 C148.2 C149.2 C150.2 CN1.1 CN1.2 CN1.3 CN1.4 CN2.1 CN2.2 CN2.3 CN2.4 CN3.5 CN3.6 CN3.7 CN3.8 CN4.1 CN4.2 CN4.3 CN4.4 CN5.5 CN5.6 CN5.7 CN5.8 CN6.1 CN6.2 CN6.3 CN6.4 CN7.5 CN7.6 CN7.7 CN7.8 CN8.5 CN8.6 CN8.7 CN8.8 D1.2 D2.2 D3.2 D4.1 D6.2 D15.2 D16.2 D18.1 D19.2(AN) D22.2(-V) IC1.4(GND) IC1.7(GND) IC1.13(AGND) IC1.17(GND) IC1.19(GND) IC1.21(RESERVED) IC1.33(GND) IC1.35(GND) IC1.48(GND) IC2.4(VSS) IC3.1 IC3.2 IC4.2(VSS) IC5.1(-VIN(GND)) IC5.7(-VOUT) IC6.A1(GND) IC6.A16(GND) IC6.B7(GND) IC6.B11(GND) IC6.D4(GND) IC6.D13(GND) IC6.E9(GND) IC6.G2(GND) IC6.G8(GND) IC6.G15(GND) IC6.H7(GND) IC6.H9(GND) IC6.H12(GND) IC6.J5(GND) IC6.J8(GND) IC6.K7(GND) IC6.K9(GND) IC6.L2(GND) IC6.L15(GND) IC6.M8(GND) IC6.N13(GND) IC6.P3(GND) IC6.R6(GND) IC6.R10(GND) IC6.T1(GND) IC6.T16(GND) IC7.7(GND) IC8.1(GND*) IC8.7(SGND) IC8.8(GND*) IC8.9(GND*) IC8.12(SYNC) IC8.16(GND*) IC9.8(E) IC10.1(NC) IC10.2(NC) IC10.3(NC) IC10.4(VSS) IC11.2(1G) IC11.4(GND) IC12.2 IC13.2(GND) IC14.4(GND) IC15.2 IC15.5 IC17.4(GND) IC18.4(VSS) IC19.2(-Vin) IC19.3(-Vin) IC20.1(GND1) IC20.3(GND1) IC20.9(GND1) IC20.10(GND1) IC21.1(~{OE}1) IC21.10(GND) IC21.19(2~{OE}) IC22.9(COM) IC22.13(GND) IC22.14(GND) IC26.2(GND) IC27.4(GND) IC27.5(GND) IC28.5 IC29.2(GND) IC30.3(GND) IC31.4(GND) IC32.2(SDI) IC32.8(VSS) IC33.14(GND) IC34.2(GND) J1.2 J1.4 J1.6 J2.1 J6.5 J7.2 J7.4 J7.6 J7.8 J7.10 J7.12 J7.14 J11.3 J11.4 J11.7 J11.8 J11.17 J12.3 J18.1 J18.2 J18.3 J18.4 J19.1 J19.2 J19.3 J19.4 J21.1 J21.2 J21.3 J21.4 J22.1 J22.2 J22.3 J22.4 J24.2 J25.1 J25.2 J25.3 J25.4 J25.5 J29.1 J29.3 J29.5 J29.7 J29.9 J29.11 J29.13 J30.1 J31.1 J32.1 J33.3 J34.1 J34.2 J34.3 J34.4 J35.2 J38.2 J39.1 J39.2 J39.3 J39.4 J40.2(-) J41.1 J41.2 J41.3 J41.4 J42.3 J43.1 J44.4 J45.1 J45.2 J45.3 J45.4 LED1.1 LED3.1 LED5.1 OP2.2(CAT) P1.5 P1.10 P1.13 P1.19 P1.26 P1.29 P1.33 P1.40 R2.2 R6.2 R28.1 R30.1 R35.2 R37.2 R43.2 R44.2 R81.1 R82.1 R83.1 R84.2 R87.1 R89.2 R92.2 R94.1 R98.2 R115.1 R116.1 R119.2 R124.2 TP2.1 TP9.1 TP11.1 TP15.1 TP111.1 TR4.2(S) TR5.2(E) TR6.2(E) TR9.2(S) TR10.1 TR11.1 TR12.1 TR13.1
GND1: C74.2 C79.1 D7.2 D8.2 IC19.16(-Vout/Common) IC25.4(GND) IC25.5(GND) J11.13 J26.1 J27.1 J37.6 LED2.1 OP1.5(GND) R86.1 TP7.1
V+: C147.1 IC26.5(VIN) IC34.5(OUT)
VCC: C140.2 C142.1 IC8.4(VCC) IC29.4(VIN) L8.2 L9.1 R120.1
VREF_2V048: C88.1 C90.2 C91.1 C93.2 C106.1 C107.1 C130.2 C131.2 C132.1 D22.1(+V) J32.2 R47.2 R54.1 R68.1 R71.1 R72.1 R99.2 R102.1 R105.2 R107.1 R108.2 R113.1
12V_EXT_EN: IC6.R2(IO_L32P_M3DQ14_3) R34.1 R35.1 TR4.1(G)
485_DE: IC6.R15(IO_L49P_M1DQ10_1) IC20.6(DE)
485_RE#: IC6.P15(IO_L48P_HDC_M1DQ8_1) IC20.5(RE#)
485_RXD: IC6.N14(IO_L45P_A1_M1LDQS_1) IC20.4(RXD)
485_TX: IC6.T15(IO_L50N_M1UDQSN_1) IC20.7(TXD)
+5VSW_EN: IC6.P2(IO_L33P_M3DQ12_3) J20.3 R74.2 R116.2 R117.1 TR9.1(G)
ADC_BUSY: IC22.16(BUSY)
ADC_CS#: IC6.T13(IO_L51N_M1DQ13_1) IC22.18(CS#)
CH4: IC6.N4(IO_L2N_3) IC22.5(CH4) R88.2 R89.1
CLKOUT: IC32.7(CLKOUT)
COMP_INB-: D20.3 IC22.3(CH2) IC33.6 R107.2 R109.2
COMP_IND-: D21.3 IC22.4(CH3) IC33.12 R108.1 R111.2
COMP_OUTA: IC6.H15(IO_L37P_A7_M1A0_1) IC33.2(OUTA) R46.2 R55.2 TP17.1
COMP_OUTB: IC6.M15(IO_L46P_FCS_B_M1DQ2_1) IC33.1(OUTB) R101.2 R103.1 TP24.1
COMP_OUTC: IC6.J14(IO_L43P_GCLK5_M1DQ4_1) IC33.16 J20.5 R45.2 R48.2 TP16.1
COMP_OUTD: IC6.L14(IO_L47P_FWE_B_M1DQ0_1) IC33.15 R104.1 R106.2 TP25.1
EEPROM1_CS#: IC2.1(CS#) IC6.M11(IO_L2N_CMPMOSI_2)
EEPROM1_SCK: IC2.6(SCK) IC6.R7(IO_L32P_GCLK29_2)
EEPROM1_SI: IC2.5(SI) IC6.P4(IO_L63P_2)
EEPROM1_SO: IC2.2(SO) IC6.K12(IO_L42P_GCLK7_M1UDM_1)
EEPROM_CLK: IC1.22(SCL) IC6.C4(IO_L1P_HSWAPEN_0) IC10.6(SCL) IC15.1 R10.1
EEPROM_SDA: IC1.23(SDA) IC6.A3(IO_L83N_VREF_3) IC10.5(SDA) IC15.3 R11.1
EN2: R96.2 TR9.3(D)
EXP_TX: J26.3 J27.3 R65.1
FANS_EN: IC6.T5(IO_L48N_RDWR_B_VREF_2) IC27.2(IN)
FD0: IC1.25(FD0) IC6.K5(IO_L47P_M3A0_3)
FD1: IC1.26(FD1) IC6.L3(IO_L36P_M3DQ8_3)
FD2: IC1.27(FD2) IC6.M1(IO_L35N_M3DQ11_3)
FD3: IC1.28(FD3) IC6.M2(IO_L35P_M3DQ10_3)
FD4: IC1.29(FD4) IC6.K3(IO_L42P_GCLK25_TRDY2_M3UDM_3)
FD5: IC1.30(FD5) IC6.K2(IO_L37P_M3DQ0_3)
FD6: IC1.31(FD6) IC6.K1(IO_L37N_M3DQ1_3)
FD7: IC1.32(FD7) IC6.J6(IO_L43P_GCLK23_M3RASN_3)
FD8: IC1.52(FD8) IC6.F4(IO_L53P_M3CKE_3)
FD9: IC1.53(FD9) IC6.E2(IO_L46P_M3CLK_3)
FD10: IC1.54(FD10) IC6.G6(IO_L51P_M3A10_3)
FD11: IC1.55(FD11) IC6.D1(IO_L49N_M3A2_3)
FD12: IC1.56(FD12) IC6.C2(IO_L48N_M3BA1_3)
FD13: IC1.1(FD13) IC6.E3(IO_L54N_M3A11_3)
FD14: IC1.2(FD14) IC6.F5(IO_L55N_M3A14_3)
FD15: IC1.3(FD15) IC6.C1(IO_L50P_M3WE_3)
FIFOADR0: IC1.44(FIFOADR0) IC6.G3(IO_L40P_M3DQ6_3)
FIFOADR1: IC1.45(FIFOADR1) IC6.F1(IO_L41N_GCLK26_M3DQ5_3)
FIFOADR2: IC1.43(FIFOADR2) IC6.G1(IO_L40N_M3DQ7_3)
FLAGA: IC1.36(FLAGA) IC6.J4(IO_L42N_GCLK24_M3LDM_3)
FLAGB: IC1.37(FLAGB) IC6.J3(IO_L38P_M3DQ2_3)
FLAGC: IC1.38(FLAGC) IC6.J1(IO_L38N_M3DQ3_3)
FLAGD/CS#: IC1.47(FLAGD/CS#) IC6.F3(IO_L53N_M3A12_3)
FLASH_CS#: IC6.T3(IO_L65N_CSO_B_2) IC14.1(/CS) J17.6
FLASH_IO0: IC6.T10(IO_L3N_MOSI_CSI_B_MISO0_2) IC14.5(DI/IO0) J17.5
FLASH_IO1: IC6.P10(IO_L3P_D0_DIN_MISO_MISO1_2) IC14.2(DO/IO1) J17.7
FLASH_IO2: IC14.3(IO2)
FLASH_IO3: IC14.7(IO3)
FLASH_SPI_CLK: IC6.R11(IO_L1P_CCLK_2) IC14.6(CLK) J17.4 R28.2 R29.2
IC6-A2: IC6.A2(IO_L52N_M3A9_3) P1.35 R84.1
IC6-A5: IC6.A5(IO_L2N_0)
IC6-A9: IC6.A9(IO_L34N_GCLK18_0) J2.2
IC6-A10: IC6.A10(IO_L35N_GCLK16_0) IC9.4(4B)
IC6-A11: IC6.A11(IO_L39N_0) J10.2
IC6-A13: IC6.A13(IO_L63N_SCP6_0) IC9.1(1B)
IC6-A14: IC6.A14(IO_L65N_SCP2_0)
IC6-B1: IC6.B1(IO_L50N_M3BA2_3) P1.30
IC6-B2: IC6.B2(IO_L52P_M3A8_3) J42.1
IC6-B3: IC6.B3(IO_L83P_3)
IC6-B5: IC6.B5(IO_L2P_0) P1.32
IC6-B6: IC6.B6(IO_L4P_0)
IC6-B10: IC6.B10(IO_L35P_GCLK17_0) J10.1
IC6-B14: IC6.B14(IO_L65P_SCP3_0) IC9.7(7B) J10.6
IC6-B15: IC6.B15(IO_L29P_A23_M1A13_1) J10.8
IC6-B16: IC6.B16(IO_L29N_A22_M1A14_1) J10.9
IC6-C3: IC6.C3(IO_L48P_M3BA0_3)
IC6-C5: IC6.C5(IO_L3N_0) P1.14
IC6-C10: IC6.C10(IO_L37N_GCLK12_0) J10.4
IC6-C11: IC6.C11(IO_L39P_0) J10.5
IC6-C13: IC6.C13(IO_L63P_SCP7_0)
IC6-C15: IC6.C15(IO_L33P_A15_M1A10_1) J10.10
IC6-C16: IC6.C16(IO_L33N_A14_M1A4_1) J10.12
IC6-D3: IC6.D3(IO_L49P_M3A7_3) J42.2
IC6-D5: IC6.D5(IO_L3P_0)
IC6-D6: IC6.D6(IO_L7P_0)
IC6-D9: IC6.D9(IO_L40N_0) J10.3
IC6-D11: IC6.D11(IO_L66P_SCP1_0) IC9.3(3B)
IC6-D12: IC6.D12(IO_L66N_SCP0_0) J10.7
IC6-D14: IC6.D14(IO_L31P_A19_M1CKE_1) J10.11
IC6-D16: IC6.D16(IO_L31N_A18_M1A12_1) J10.14
IC6-E8: IC6.E8(IO_L36N_GCLK14_0) IC9.5(5B)
IC6-E10: IC6.E10(IO_L37P_GCLK13_0) IC9.2(2B)
IC6-E11: IC6.E11(IO_L64N_SCP4_0) IC9.6(6B)
IC6-E12: IC6.E12(IO_L1N_A24_VREF_1) J10.13
IC6-E15: IC6.E15(IO_L34P_A13_M1WE_1)
IC6-E16: IC6.E16(IO_L34N_A12_M1BA2_1)
IC6-F6: IC6.F6(IO_L55P_M3A13_3)
IC6-F9: IC6.F9(IO_L40P_0)
IC6-F10: IC6.F10(IO_L64P_SCP5_0) J10.15
IC6-F12: IC6.F12(IO_L30P_A21_M1RESET_1) J10.16
IC6-F13: IC6.F13(IO_L32P_A17_M1A8_1)
IC6-F14: IC6.F14(IO_L32N_A16_M1A9_1)
IC6-F15: IC6.F15(IO_L35P_A11_M1A7_1) J10.18
IC6-F16: IC6.F16(IO_L35N_A10_M1A2_1) J10.17
IC6-G11: IC6.G11(IO_L30N_A20_M1A11_1) IC21.9(2Y3)
IC6-G12: IC6.G12(IO_L38P_A5_M1CLK_1)
IC6-G14: IC6.G14(IO_L36P_A9_M1BA0_1)
IC6-G16: IC6.G16(IO_L36N_A8_M1BA1_1) J10.19
IC6-H3: IC6.H3(IO_L44N_GCLK20_M3A6_3) R14.1
IC6-H13: IC6.H13(IO_L39P_M1A3_1) IC21.5(2Y1)
IC6-H16: IC6.H16(IO_L37N_A6_M1A1_1) J10.20
IC6-K6: IC6.K6(IO_L47N_M3A1_3) R110.2
IC6-K14: IC6.K14(IO_L41N_GCLK8_M1CASN_1) IC21.8(I3)
IC6-K16: IC6.K16(IO_L44N_A2_M1DQ7_1)
IC6-L5: IC6.L5(IO_L45N_M3ODT_3)
IC6-L7: IC6.L7(IO_L62N_D6_2)
IC6-L8: IC6.L8(IO_L62P_D5_2)
IC6-L10: IC6.L10(IO_L16P_2)
IC6-L13: IC6.L13(IO_L53N_VREF_1) IC21.13(2A2) IC29.3(EN)
IC6-L16: IC6.L16(IO_L47N_LDC_M1DQ1_1) IC21.6(I2)
IC6-M4: IC6.M4(IO_L1P_3) R132.2
IC6-M5: IC6.M5(IO_L2P_3)
IC6-M6: IC6.M6(IO_L64P_D8_2)
IC6-M7: IC6.M7(IO_L31N_GCLK30_D15_2) R127.2
IC6-M9: IC6.M9(IO_L29P_GCLK3_2)
IC6-M10: IC6.M10(IO_L16N_VREF_2)
IC6-N3: IC6.N3(IO_L34P_M3UDQS_3) R131.2
IC6-N5: IC6.N5(IO_L49P_D3_2)
IC6-N6: IC6.N6(IO_L64N_D9_2)
IC6-N8: IC6.N8(IO_L29N_GCLK2_2)
IC6-N9: IC6.N9(IO_L14P_D11_2)
IC6-N16: IC6.N16(IO_L45N_A0_M1LDQSN_1)
IC6-P5: IC6.P5(IO_L49N_D4_2)
IC6-P6: IC6.P6(IO_L47P_2) R126.2
IC6-P7: IC6.P7(IO_L31P_GCLK31_D14_2) R218.1
IC6-P8: IC6.P8(IO_L30P_GCLK1_D13_2)
IC6-P9: IC6.P9(IO_L14N_D12_2)
IC6-P11: IC6.P11(IO_L13N_D10_2)
IC6-P16: IC6.P16(IO_L48N_M1DQ9_1)
IC6-R9: IC6.R9(IO_L23P_2)
IC6-R16: IC6.R16(IO_L49N_M1DQ11_1)
IC6-T4: IC6.T4(IO_L63N_2)
IC6-T7: IC6.T7(IO_L32N_GCLK28_2)
IC6-T8: IC6.T8(IO_L30N_GCLK0_USERCCLK_2)
IC6-T9: IC6.T9(IO_L23N_2)
IC7-3: IC6.E7(IO_L36P_GCLK15_0) IC7.3(1Y) P1.17
IC7-5: IC6.A8(IO_L33N_0) IC7.5(2A) P1.12
IC7-9: IC6.D8(IO_L38P_0) IC7.9(3A) P1.15
IC13-4: IC6.N1(IO_L34N_M3UDQSN_3) IC13.4(SCLK) R20.2
IC13-5: IC6.M3(IO_L1N_VREF_3) IC13.5(SDA) R24.2
IC21-2: IC6.M16(IO_L46N_FOE_B_M1DQ3_1) IC21.2(I0)
IC21-4: IC6.J13(IO_L41P_GCLK9_IRDY1_M1RASN_1) IC21.4(I1)
IC28-3: IC6.H11(IO_L38N_A4_M1CLKN_1) IC28.1 IC28.3 R92.1 TP20.1
IFCLK: IC1.20(IFCLK) IC6.L1(IO_L36N_M3DQ9_3)
J17-3: IC6.N11(IO_L13P_M1_2) J17.3 R30.2
LVT244_IN4: IC6.M14(IO_L74N_DOUT_BUSY_1) IC21.17(2A0)
OE: IC6.B8(IO_L33P_0) IC7.1(1~{O}E) IC7.4(2~{OE}) IC7.10(3~{OE}) IC7.13(4~{OE}) R5.1 R6.1
OPA1_OUTB: C83.2 IC22.2(CH1) IC23.6(-) IC23.7(OUT) IC33.4(INA-1)
OPA2_OUTB: C86.2 IC22.1(CH0) IC24.6(-) IC24.7(OUT) IC33.10
P1-16: IC6.A4(IO_L1N_VREF_0) P1.16
P1-20: IC6.E4(IO_L54P_M3RESET_3) P1.20
P1-21: IC6.C8(IO_L38N_VREF_0) IC7.12(4A) P1.21
PKTEND: IC1.46(PKTEND) IC6.G5(IO_L51N_M3A4_3)
R26-2: IC6.R3(IO_L65P_INIT_B_2) J17.9 R26.2
R27-2: IC6.T11(IO_L1N_M0_CMPMISO_2) J17.8 R27.2
R33-2: IC6.K15(IO_L44P_A3_M1DQ6_1) R33.2
R36-1: IC6.H14(IO_L39N_M1ODT_1) IC17.1(CLKIN) R36.1 R37.1
R98-1: IC6.R5(IO_L48P_D7_2) IC31.1(CLKIN) R97.2 R98.1
R128-2: IC6.T6(IO_L47N_2) R128.2
R130-2: IC6.P1(IO_L33N_M3DQ13_3) R130.2
RTC_CLK: IC32.1(SCL) P1.6
RTC_SDA: IC32.4(SDA/CE#) P1.4
SD: IC6.E6(IO_L5N_0) J20.4 P1.38
SERIAL_EXP_RX: IC6.M13(IO_L74P_AWAKE_1) OP2.1(AN)
SERIAL_EXP_TX: IC6.T14(IO_L51P_M1DQ12_1) R42.2
SHDN#: IC6.E13(IO_L1P_A25_1) IC8.3(SHDN#) IC26.4(SHDN#)
SLRD: IC1.8(SLRD) IC6.E1(IO_L46N_M3CLKN_3)
SLWR: IC1.9(SLWR) IC6.H1(IO_L39N_M3LDQSN_3)
SPI_CK: IC6.P12(IO_L12N_D2_MISO3_2) IC18.6(SCK) IC22.19(DCLK)
SPI_MISO: IC6.R14(IO_L50P_M1UDQS_1) IC18.2(SO/SIO1) R114.2 R115.2
SPI_MOSI: IC6.M12(IO_L2P_CMPCLK_2) IC18.5(SI/SIO0) IC22.17(DIN)
SRAM_CS#: IC6.R12(IO_L52P_M1DQ14_1) IC18.1(CS#)
SRAM_HOD#: IC6.N12(IO_L12P_D1_MISO2_2) IC18.7(HOLD#/SIO3)
SRAM_SIO2: IC6.T12(IO_L52N_M1DQ15_1) IC18.3(SIO2)
TCK: IC6.C14(TCK) IC7.8(3Y) J7.9
TDI: IC6.C12(TDI) IC7.11(4Y) J7.5
TDO: IC6.E14(TDO) IC7.2(1A) J7.7
TMS: IC6.A15(TMS) IC7.6(2Y) J7.11
USB_DEVICE_INT#: IC1.41(INT#) IC6.H4(IO_L44P_GCLK21_M3A5_3)
USB_DEVICE_READY: IC1.40(READY) IC6.H2(IO_L39P_M3LDQS_3)
USB_DEVICE_RSET#_WAKUP: IC1.49(RESET#) IC1.51(WAKEUP) IC6.F2(IO_L41P_GCLK27_M3DQ4_3) R9.2
USB_DEVICE_SLOE: IC1.42(SLOE) IC6.H5(IO_L43N_GCLK22_IRDY2_M3CASN_3)
XTAL_OUT: IC1.11(XTALOUT)
NetC43_1: C43.1 IC13.1(VDD) R25.1
NetC44_2: C44.2 IC6.T2(PROGRAM_B_2) R21.2 TP21.1
NetC54_1: C54.1 J1.3 TR2.2 TR2.3
NetC55_2: C55.2 J1.5 TR3.2 TR3.3
NetC71_2: C71.2 IC19.22(+Vin) IC19.23(+Vin) L6.1
NetC83_1: C83.1 R56.2 R62.1
NetC86_1: C86.1 R57.2 R63.1
NetC88_2: C88.2 IC23.5(+) R56.1
NetC90_1: C90.1 D10.3 D14.1 D14.2 IC23.3(+) R68.2 R69.2
NetC91_2: C91.2 IC24.5(+) R57.1
NetC93_1: C93.1 D11.3 IC24.3(+) R72.2 R73.2
NetC94_2: C94.2 R118.2
NetC96_2: C96.2 J25.9 TR10.2 TR10.3
NetC97_2: C97.2 J25.8 TR11.2 TR11.3
NetC98_2: C98.2 J25.7 TR12.2 TR12.3
NetC99_1: C99.1 J25.6 TP19.1 TR13.2 TR13.3
NetC100_1: C100.1 C101.1 C102.2 C103.2 IC20.11(GND2) IC20.14(GND2) IC20.16(GND2) IC20.20(GND2) R86.2
NetC100_2: C100.2 C101.2 C102.1 C103.1 IC20.12(VISOOUT) IC20.19(VISOIN)
NetC104_1: C104.1 D12.3 D14.3 IC23.2(-) R66.1 R67.1
NetC104_2: C104.2 IC23.1(OUT) R66.2 R79.2
NetC105_1: C105.1 IC24.1(OUT) R70.2 R80.1
NetC105_2: C105.2 D13.3 IC24.2(-) R70.1 R71.2
NetC106_2: C106.2 R62.2 R79.1
NetC107_2: C107.2 R63.2 R80.2
NetC108_1: C108.1 R130.1 TR3.5
NetC109_1: C109.1 R131.1 TR2.5
NetC110_1: C110.1 R132.1 TR1.5
NetC111_2: C111.2 C135.1 C136.2 J25.10 L1.1 R88.1 TP18.1
NetC114_2: C114.2 L3.1 R91.1
NetC115_2: C115.2 C116.2 IC28.2 IC29.5(VREF)
NetC117_1: C117.1 R91.2
NetC117_2: C117.2 R90.1
NetC118_1: C118.1 J39.5 L7.2
NetC119_1: C119.1 L3.2 L7.1
NetC121_1: C121.1 R93.1
NetC121_2: C121.2 IC30.4(TRIM) R94.2
NetC127_2: C127.2 IC32.15(VBAT) J40.1(+)
NetC128_2: C128.2 IC32.5(IFS) IC32.14(BBS)
NetC129_1: C129.1 D19.1(CAT) IC22.11(VREF) R112.1
NetC138_1: C138.1 IC8.14(VC) R118.1
NetC141_2: C141.2 IC8.2(NC)
NetC144_2: C144.2 C145.1 L10.1 L11.3 R123.1
NetC145_2: C145.2 IC26.3(NFB) R123.2 R124.1
NetC146_1: C146.1 IC26.1(SW) L11.1
NetC146_2: C146.2 D16.1 L11.4
NetC148_1: C148.1 IC34.4(BYPASS)
NetD7_1: D7.1 R59.2 R60.2
NetD8_1: D8.1 IC25.6(OUT) IC25.7(OUT) R65.2
NetD9_3: D9.3(A) OP2.5(GND) R60.1 R61.1
NetD15_1: D15.1 IC8.6(VSW) L4.2 L8.1
NetD17_1: D17.1 L1.2
NetD17_2: D17.2 IC27.7(OUT) IC27.OUT#(OUT)
NetD18_3: D18.3 IC31.3(Y0) IC31.5(Y2) IC31.7(Y3) IC31.8(Y1) R100.1
NetF1_2: F1.2 IC19.14(+Vout)
NetF2_2: F2.2 J24.1
NetF5_2: F5.2 R23.1 TR2.4
NetF6_2: F6.2 R22.1 TR1.4
NetF7_2: F7.2 R32.1 TR3.4
NetIC1_12: IC1.12(XTALIN) IC3.3
NetIC1_15: IC1.15(DPLUS) J38.3
NetIC1_16: IC1.16(DMINUS) J38.4
NetIC6_A6: IC6.A6(IO_L4N_0) J6.4
NetIC6_A7: IC6.A7(IO_L6N_0) J6.2
NetIC6_C6: IC6.C6(IO_L7N_0) J6.3
NetIC6_C7: IC6.C7(IO_L6P_0) J6.1
NetIC6_L4: IC6.L4(IO_L45P_M3A3_3) R1.2 R2.1
NetIC6_P13: IC6.P13(DONE_2) R31.1 TP6.1
NetIC8_5: IC8.5(VD) L4.1
NetIC8_13: IC8.13(FB) R119.1 R120.2
NetIC9_9: IC9.9(COM) J11.9 J11.10 R3.1 R7.1 R8.1 R12.1 R15.1 R16.1 R17.1
NetIC9_10: IC9.10(7C) J12.2
NetIC9_11: IC9.11(6C) LED7.1
NetIC9_12: IC9.12(5C) LED4.1
NetIC9_13: IC9.13(4C) LED6.1
NetIC9_14: IC9.14(3C) J8.6
NetIC9_15: IC9.15(2C) J8.4
NetIC9_16: IC9.16(1C) J8.2
NetIC11_1: IC11.1(CLKIN) IC12.3
NetIC11_3: IC11.3(Y0) R14.2
NetIC11_5: IC11.5(Y2) R18.1
NetIC11_7: IC11.7(Y3) R13.1
NetIC11_8: IC11.8(Y1) R19.2
NetIC17_3: IC17.3(Y0) R49.2
NetIC17_5: IC17.5(Y2) R50.2
NetIC17_7: IC17.7(Y3) R39.2
NetIC17_8: IC17.8(Y1) R38.1
NetIC19_1: IC19.1(Remote_On/Off) TR4.3(D)
NetIC20_13: IC20.13(Y) IC20.18(A) J37.1 J37.4 R85.1
NetIC20_15: IC20.15(Z) IC20.17(B) J37.2 J37.3 R85.2
NetIC21_3: IC21.3(2Y0) J30.2
NetIC21_7: IC21.7(2Y2) J30.3
NetIC21_11: IC21.11(2A3) J29.4
NetIC21_12: IC21.12(O3) J29.8
NetIC21_14: IC21.14(O2) J29.12
NetIC21_15: IC21.15(2A1) J29.2
NetIC21_16: IC21.16(O1) J29.10
NetIC21_18: IC21.18(O0) J29.6
NetIC22_6: IC22.6(CH5) J32.3
NetIC22_7: IC22.7(CH6) J32.4
NetIC22_8: IC22.8(CH7) J32.5
NetIC22_15: IC22.15(DouT) R114.1
NetIC25_2: IC25.2(IN) OP1.4(VO) R58.2
NetIC28_4: IC28.4 IC28.6 R90.2
NetIC30_1: IC30.1(ON/OFF) R95.1 R96.1
NetIC33_5: IC33.5(INA+1) R54.2 R55.1
NetIC33_7: IC33.7 R102.2 R103.2
NetIC33_11: IC33.11 R47.1 R48.1
NetIC33_13: IC33.13 R105.1 R106.1
NetIC34_1: IC34.1(IN) IC34.3(ON/OFF) R125.1
NetJ5_1: J5.1 J5.2 J5.3 J5.4
NetJ5_5: J5.5 J19.5 R13.2
NetJ8_1: J8.1 R8.2
NetJ8_3: J8.3 R7.2
NetJ8_5: J8.5 R3.2
NetJ9_1: J9.1 J9.2 J9.3 J9.4
NetJ9_5: J9.5 J34.5 R18.2
NetJ11_11: J11.11 J11.12
NetJ12_1: J12.1 R12.2
NetJ13_1: J13.1 J13.2 J13.3 J13.4
NetJ13_5: J13.5 J45.5 R19.1
NetJ18_5: J18.5 R39.1
NetJ20_1: J20.1 R110.1
NetJ21_5: J21.5 R50.1
NetJ22_5: J22.5 R49.1
NetJ26_4: J26.4 J27.4 R59.1
NetJ29_14: J29.14 R43.1 TR6.3(C)
NetJ31_2: J31.2 R69.1
NetJ31_3: J31.3 R67.2
NetJ33_1: J33.1 P1.9
NetJ38_1: J38.1 R87.2
NetJ41_5: J41.5 R100.2
NetJ43_2: J43.2 R133.2
NetJ43_3: J43.3 R99.1
NetJ44_1: J44.1 R109.1
NetJ44_2: J44.2 R111.1
NetLED1_2: LED1.2 R4.1
NetLED2_2: LED2.2 R53.1
NetLED3_2: LED3.2 R52.2
NetLED4_2: LED4.2 R16.2
NetLED5_2: LED5.2 R64.2
NetLED6_2: LED6.2 R15.2
NetLED7_2: LED7.2 R17.2
NetOP1_2: OP1.2(CAT) R42.1
NetR22_2: R22.2 TR1.6
NetR23_2: R23.2 TR2.6
NetR32_2: R32.2 TR3.6
NetR33_1: R33.1 TR5.1(B)
NetR38_2: R38.2 TP22.1
NetR44_1: R44.1 TR5.3(C) TR6.1(B)
NetR73_1: R73.1 R133.1
NetR75_2: R75.2 TR10.6
NetR76_2: R76.2 TR13.6
NetR77_2: R77.2 TR12.6
NetR78_2: R78.2 TR11.6
NetR81_2: R81.2 TR1.1
NetR82_2: R82.2 TR2.1
NetR83_2: R83.2 TR3.1
NetR126_1: R126.1 TR10.5
NetR127_1: R127.1 TR11.5
NetR128_1: R128.1 TR12.5
NetR218_2: R218.2 TR13.5

Not connected (* = marked no-connect by the designer): D9 1(C1); D19 3(NC); D22 3(NC); IC1 5(NC); IC4 4(NC); IC5 3(REMOTE) 5(NC) 8(NC); IC6 A12(IO_L62N_VREF_0) B12(IO_L62P_0) C9(IO_L34P_GCLK19_0) F7(IO_L5P_0) J11(IO_L40P_GCLK11_M1A5_1) J12(IO_L40N_GCLK10_M1A6_1) J16(IO_L43N_GCLK4_M1DQ5_1) K11(IO_L42N_GCLK6_TRDY1_M1LDM_1) L11(CMPCS_B_2) L12(IO_L53P_1) P14(SUSPEND) R1(IO_L32N_M3DQ15_3); IC8 11(NC) 15(NC); IC10 7(WP); IC12 1; IC13 3(ALERT); IC19 9(No_Pin/Common) 11(Not_Connected/-Vout); IC25 3(NC); IC27 3(NC); IC29 1(N/C); IC32 3(SDO) 6(TS#) 9(NC) 10(NC) 11(NC) 12(NC) 13(INT#); IC33 8(REF); J7 1 3; J17 1; J32 6 7 8; OP1 3(NC); OP2 6(VCC); P1 8 11 18 22 23 24 25 27 28 31 34 36 37 39; TP1 1

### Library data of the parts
C1 C2 C4-C7 C12-C51 C54-C57 C61 C68 C69 C72 C74-C86 C88-C134 C136-C141 C143-C150 = CAP: Capacitor
C67 C70 C71 C135 C142 = EC: Electrolytic Capacitor
CN1-CN8 = CAP_8
D1-D4 D6-D8 = DZ
D9 = BAW56W-7-F: Contributor: LCSC
D10-D13 D18 D20 D21 = BAV99: BOM_Manufacturer: CJ; SMT Type: Extend
D14 = BAV99W
D15-D17 = DDDDX
D19 = LM4040AIM3X-4.1/NOPB: Contributor: LCSC
D22 = LM4040CIM3-2.0/NOPB: Contributor: LCSC
F1 F2 F5-F7 = R_fuse
IC1 = CY7C68001-56PVXC: Contributor: LCSC
IC3 IC12 = JT_4
IC4 = XC6210B122MR-G: Contributor: LCSC
IC5 = TMR 1210
IC6 = XC6SLX25-2FTG256I: subpart_no: 1; Contributor: LCSC
IC7 = SN74AHC125PWR_1
IC8 = LT1777IS#PBF: Contributor: LCSC
IC10 = 24LC08B/P: Contributor: lcsc
IC11 IC17 IC31 = CDCLVC1104PWR: Contributor: LCSC
IC13 = MCP9802A0T-M/OT: Contributor: lcsc
IC15 = DIP5
IC18 = 23LC1024-I/ST: Contributor: LCSC
IC19 = JCG1212S05: Manufacturer: null; Contributor: LCSC
IC21 = 74AC244MTC
IC22 = ADS7844E/2K5: Contributor: lcsc
IC23 IC24 = LM358A
IC28 = NMOS+PMOS  SOP6
IC29 = LM4128AMF-3.3/NOPB: Contributor: LCSC
IC32 = PCF2129T/2,518: Contributor: LCSC
IC33 = MAX974ESE+: 14PIN 4+ 11- OUT_ 1 7 8 14
IC34 = LP2985IM5X-5.0/NOPB: Contributor: LCSC
J1 = COON6X: Connector
J2 J12 J31 J33 J35 J42 J43 = CON3: Connector
J5 J9 J13 J18 J19 J21 J22 J34 J39 J41 J45 = RF_5_1_1
J6 J20 J38 = CON5: Connector
J7 J29 = COON14X: Connector
J8 J37 = CON6: Connector
J10 = CON20: Connector
J11 = CON18: Connector
J17 J25 = CON10: Connector
J24 = CON2: Connector
J26 J27 J30 J44 = CON4: Connector
J32 = CON8: Connector
J40 = BATTERY
L1 L3 L5 L7-L10 = LLL1
L4 L6 = LLL2
L11 = UU9.8
LED1-LED7 = LEDA
OP1 OP2 = H11L1S1(TA)-V: Contributor: lcsc
P1 = COON40X: Connector
R1-R39 R42-R50 R52-R120 R123-R128 R130-R133 R218 = R_XIAO
TP1 TP2 TP4-TP22 TP24 TP25 TP111 = TTT_DWK1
